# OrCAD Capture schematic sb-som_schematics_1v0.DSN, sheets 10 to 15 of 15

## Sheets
10 03. CompuLab CoM/SoM: size C; title: SB-SOM    03. CompuLab CoM/SoM
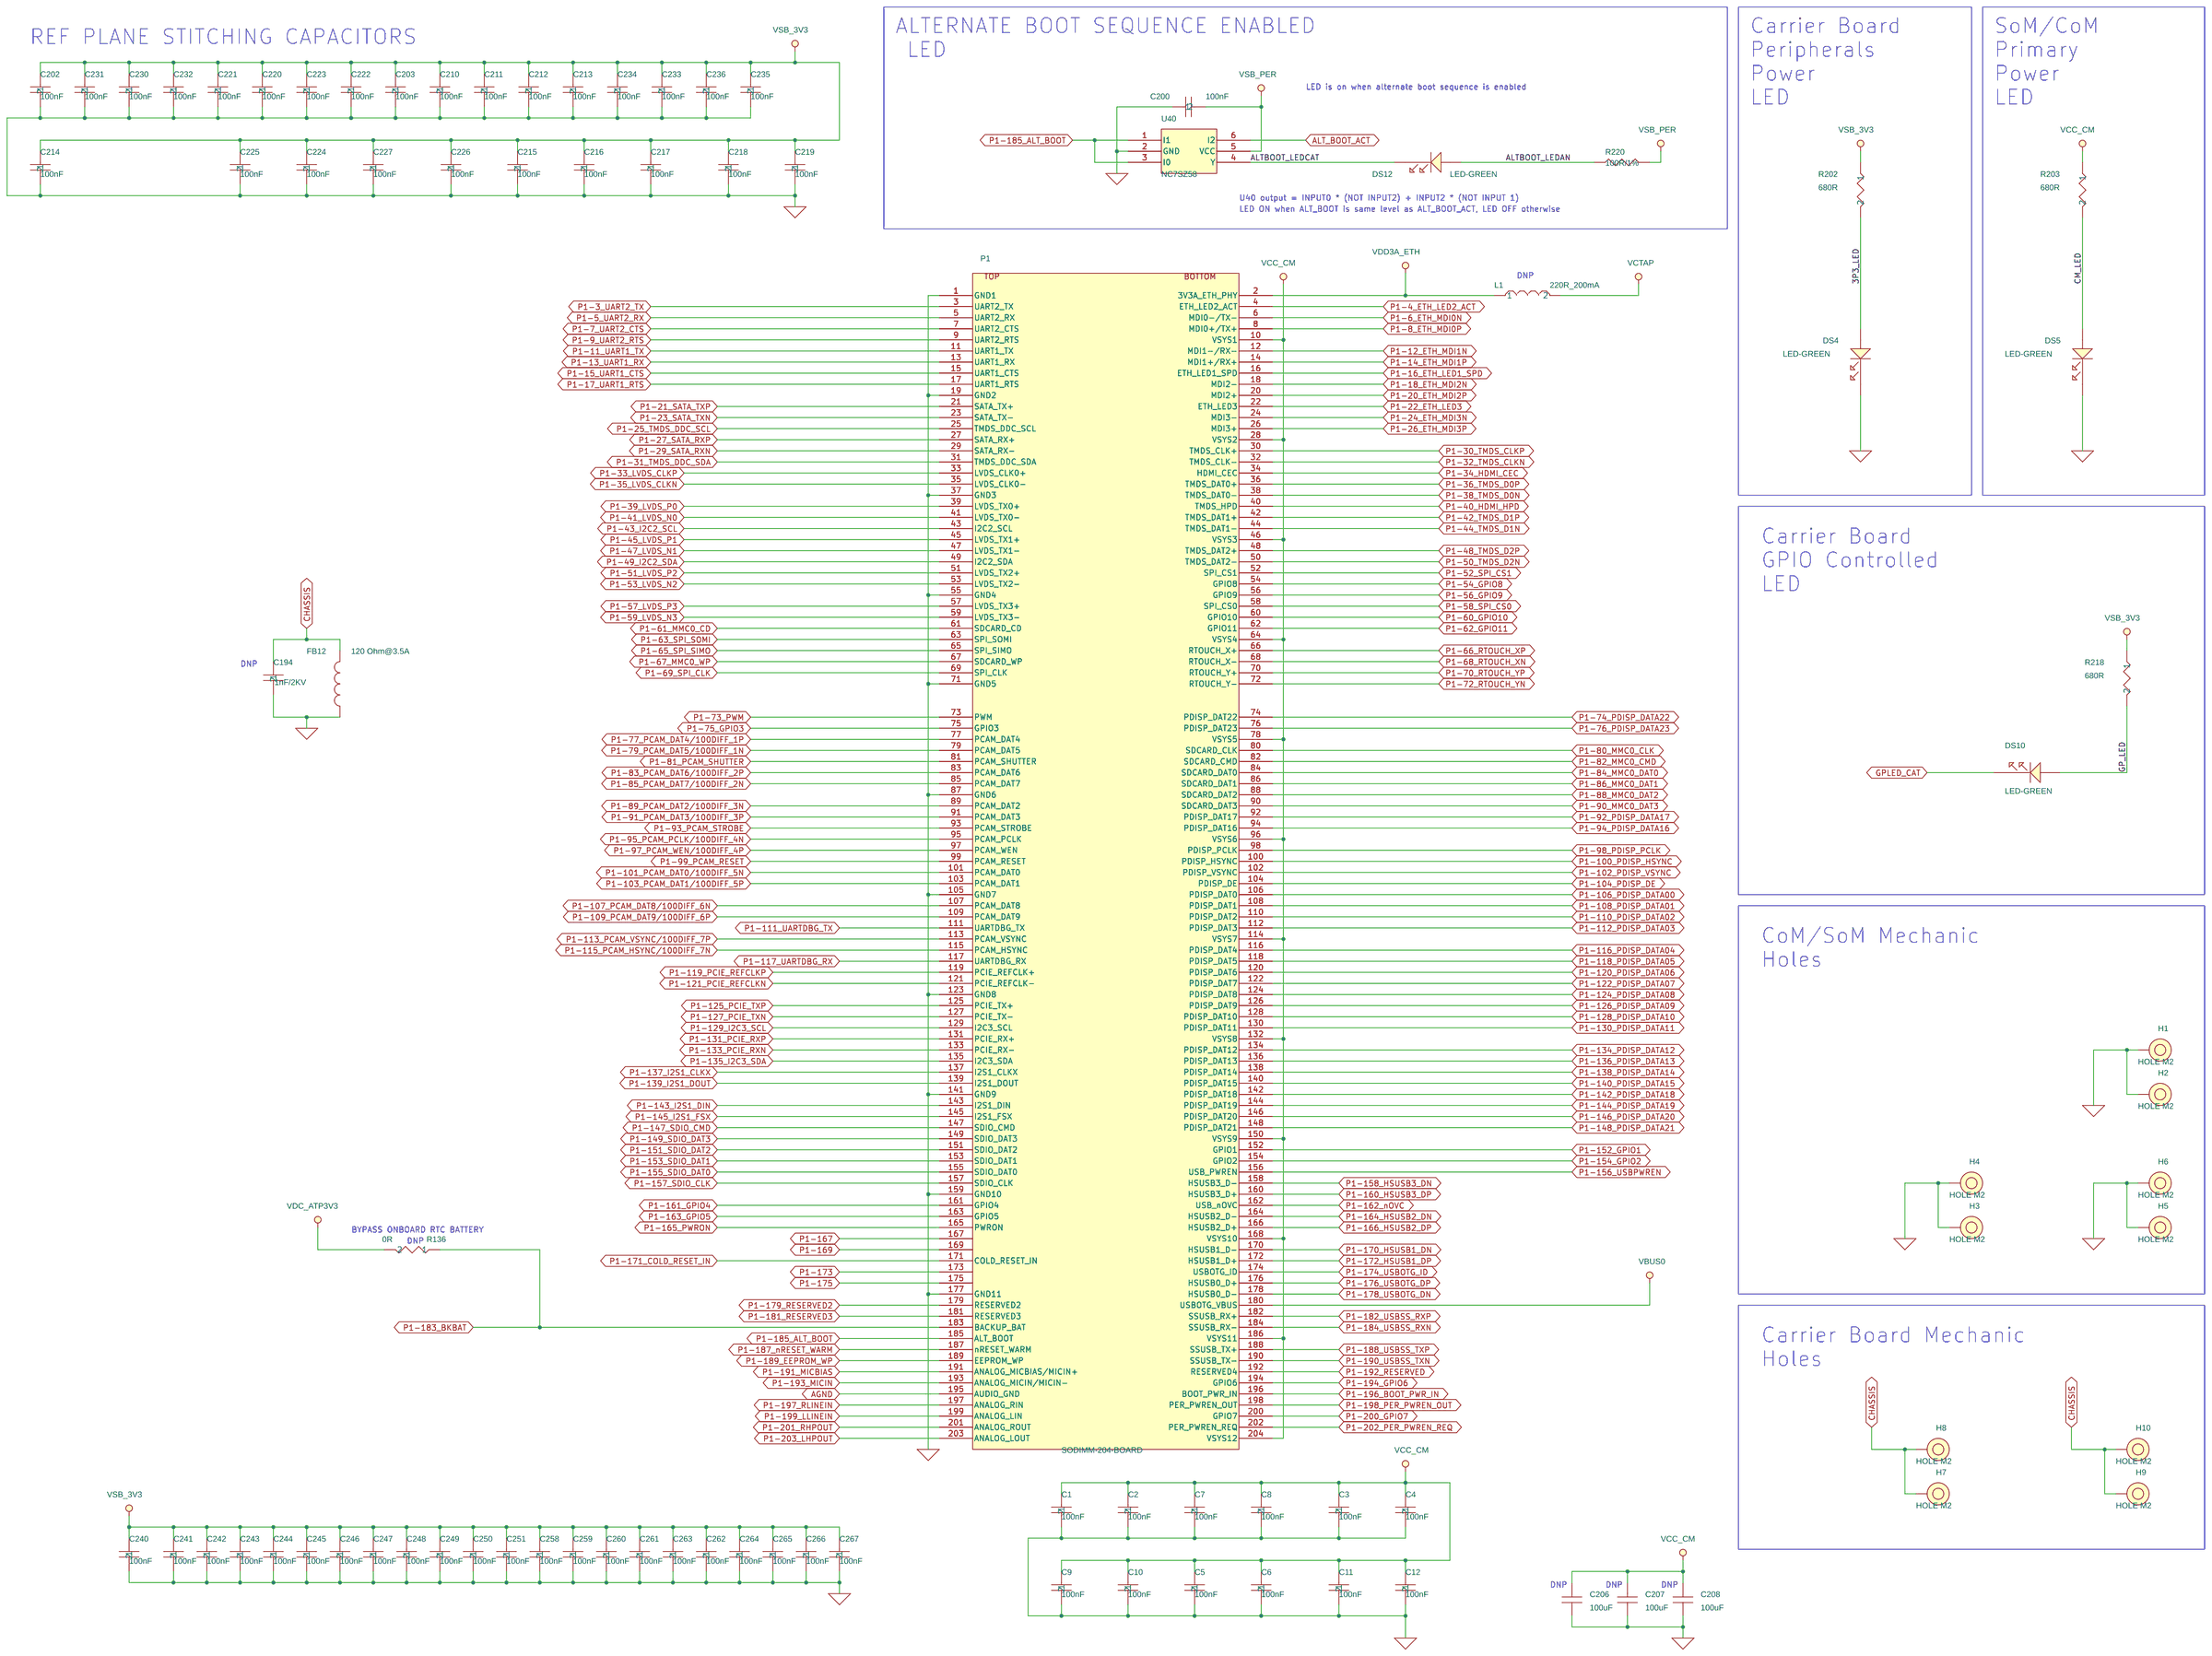
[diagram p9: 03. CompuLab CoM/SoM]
11 12. Bypass: CM-T54 Specific: size C; title: SB-SOM    12. Bypass: CM-T54 Specific
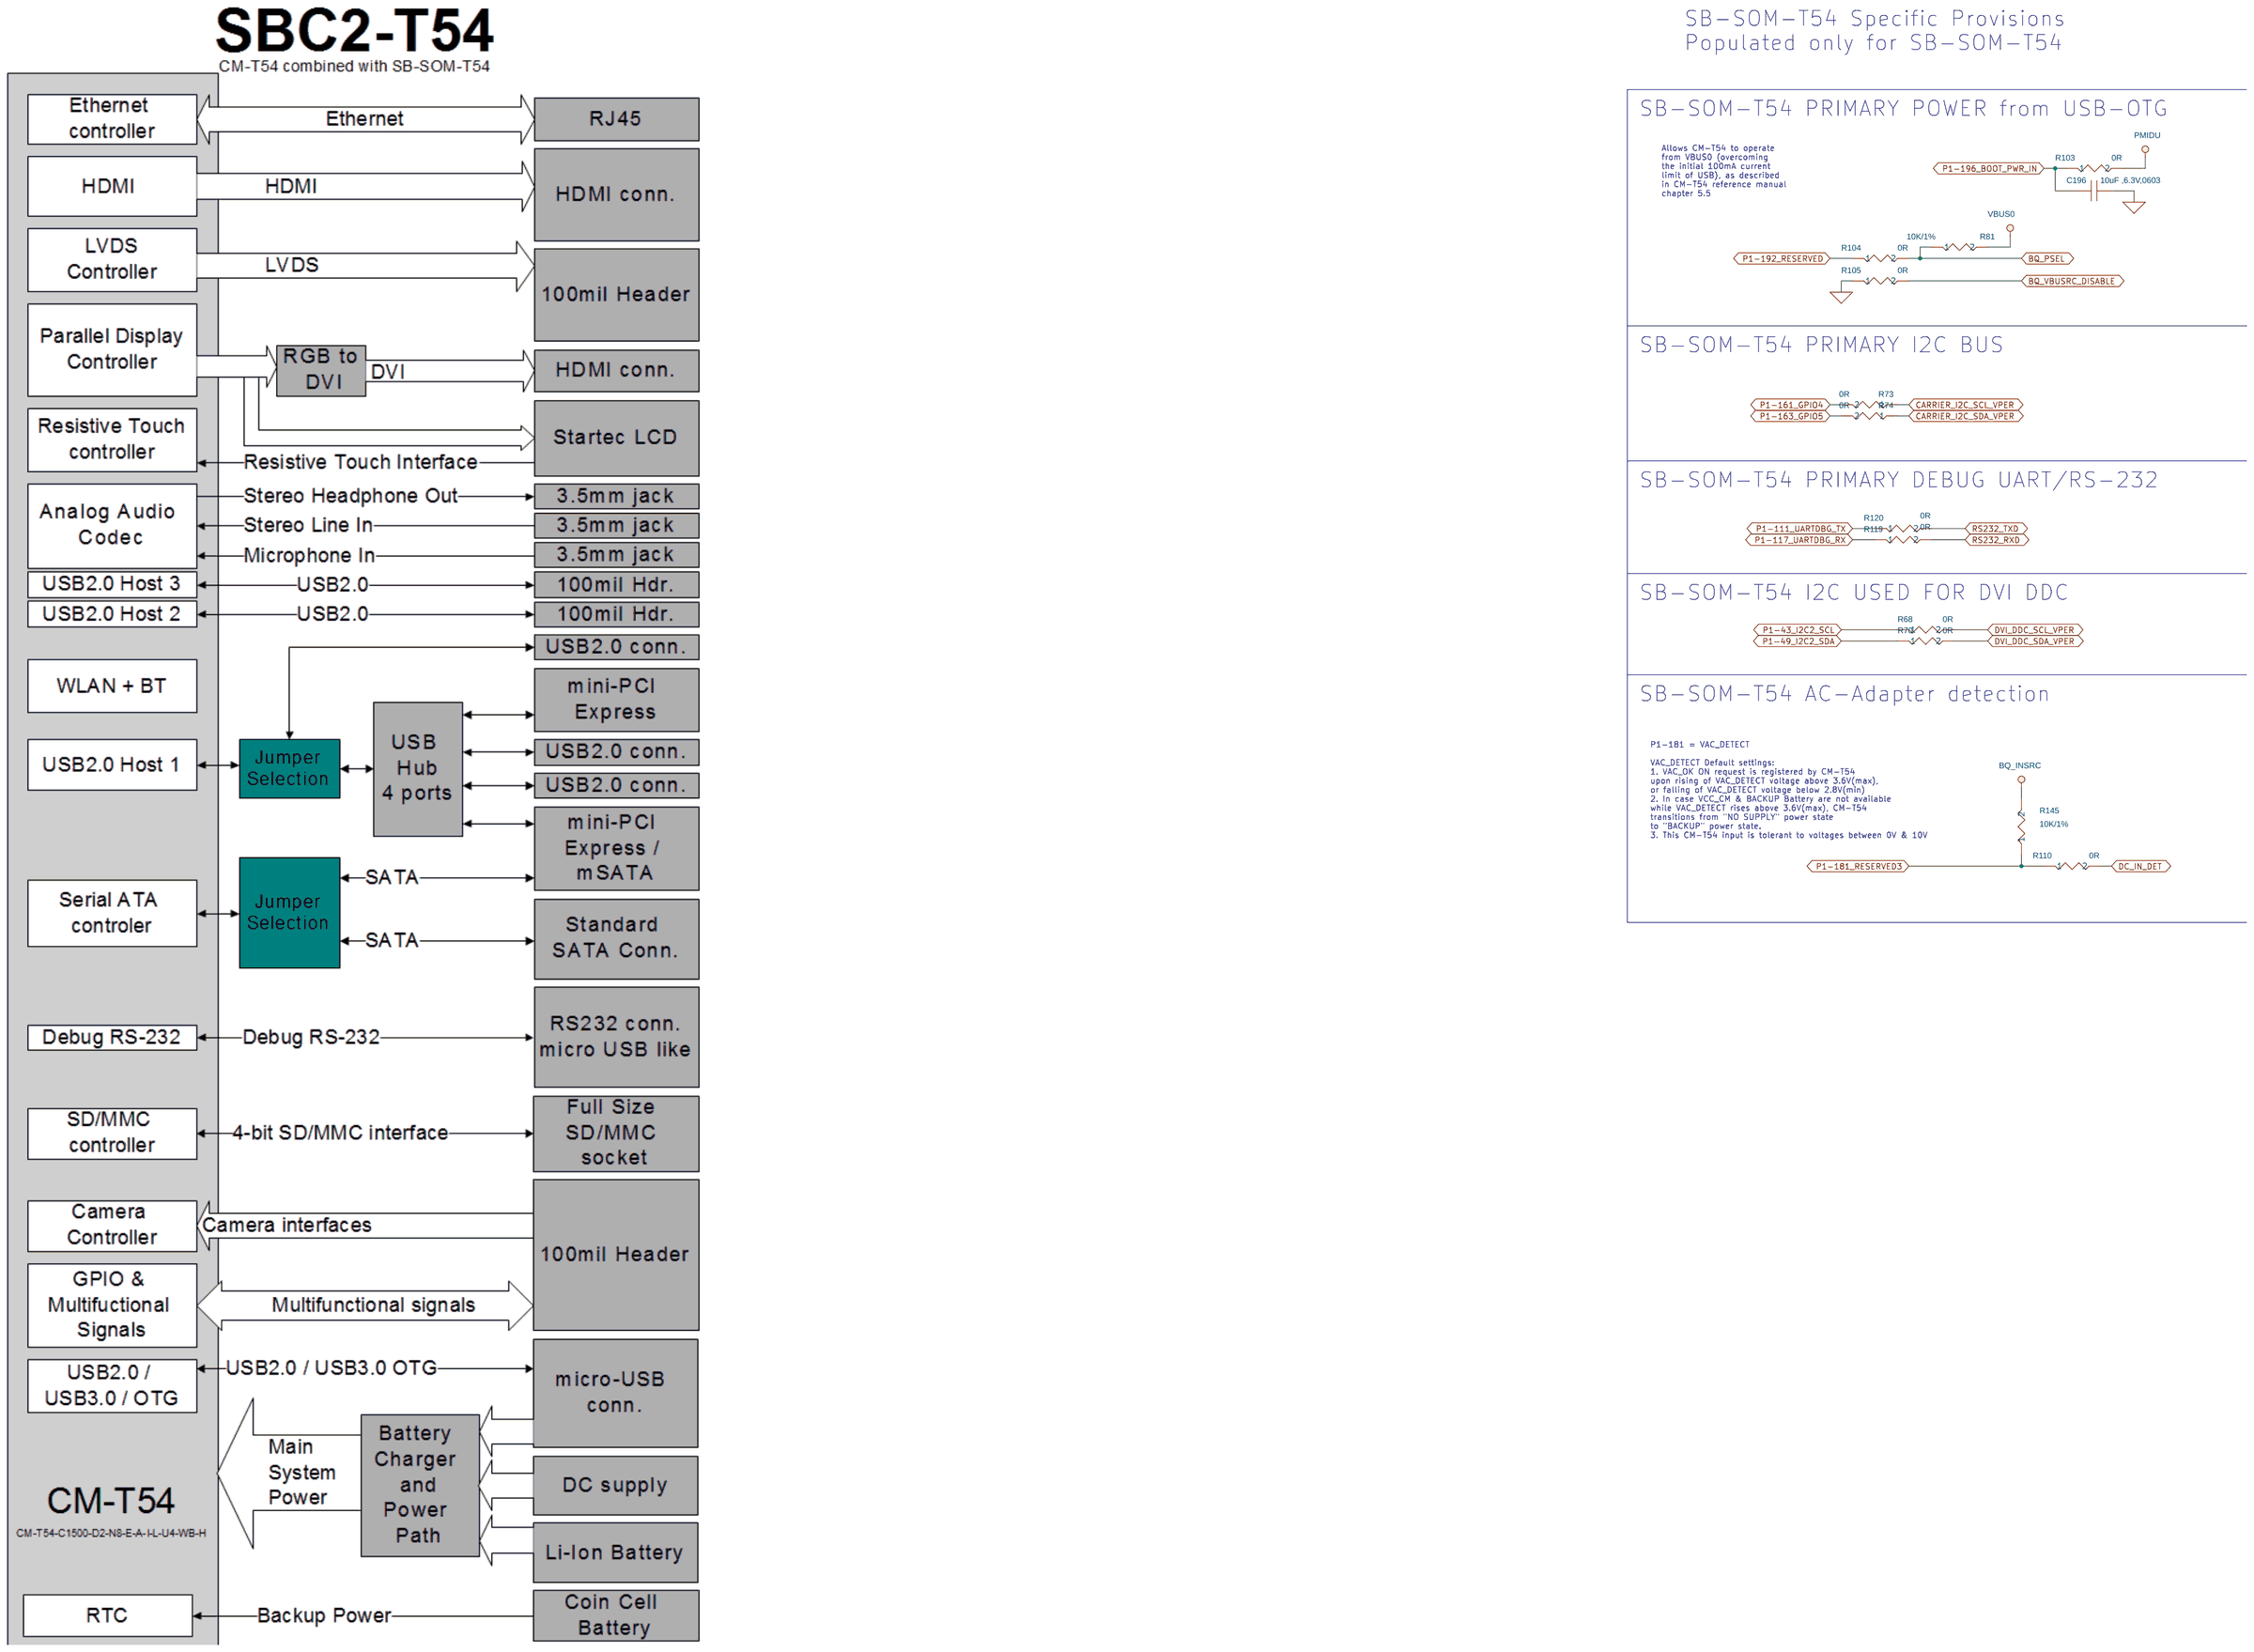
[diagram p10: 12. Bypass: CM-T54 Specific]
12 11. Bypass: non-SoM-Specific: size C; title: SB-SOM    11. Bypass: non-SoM-Specific
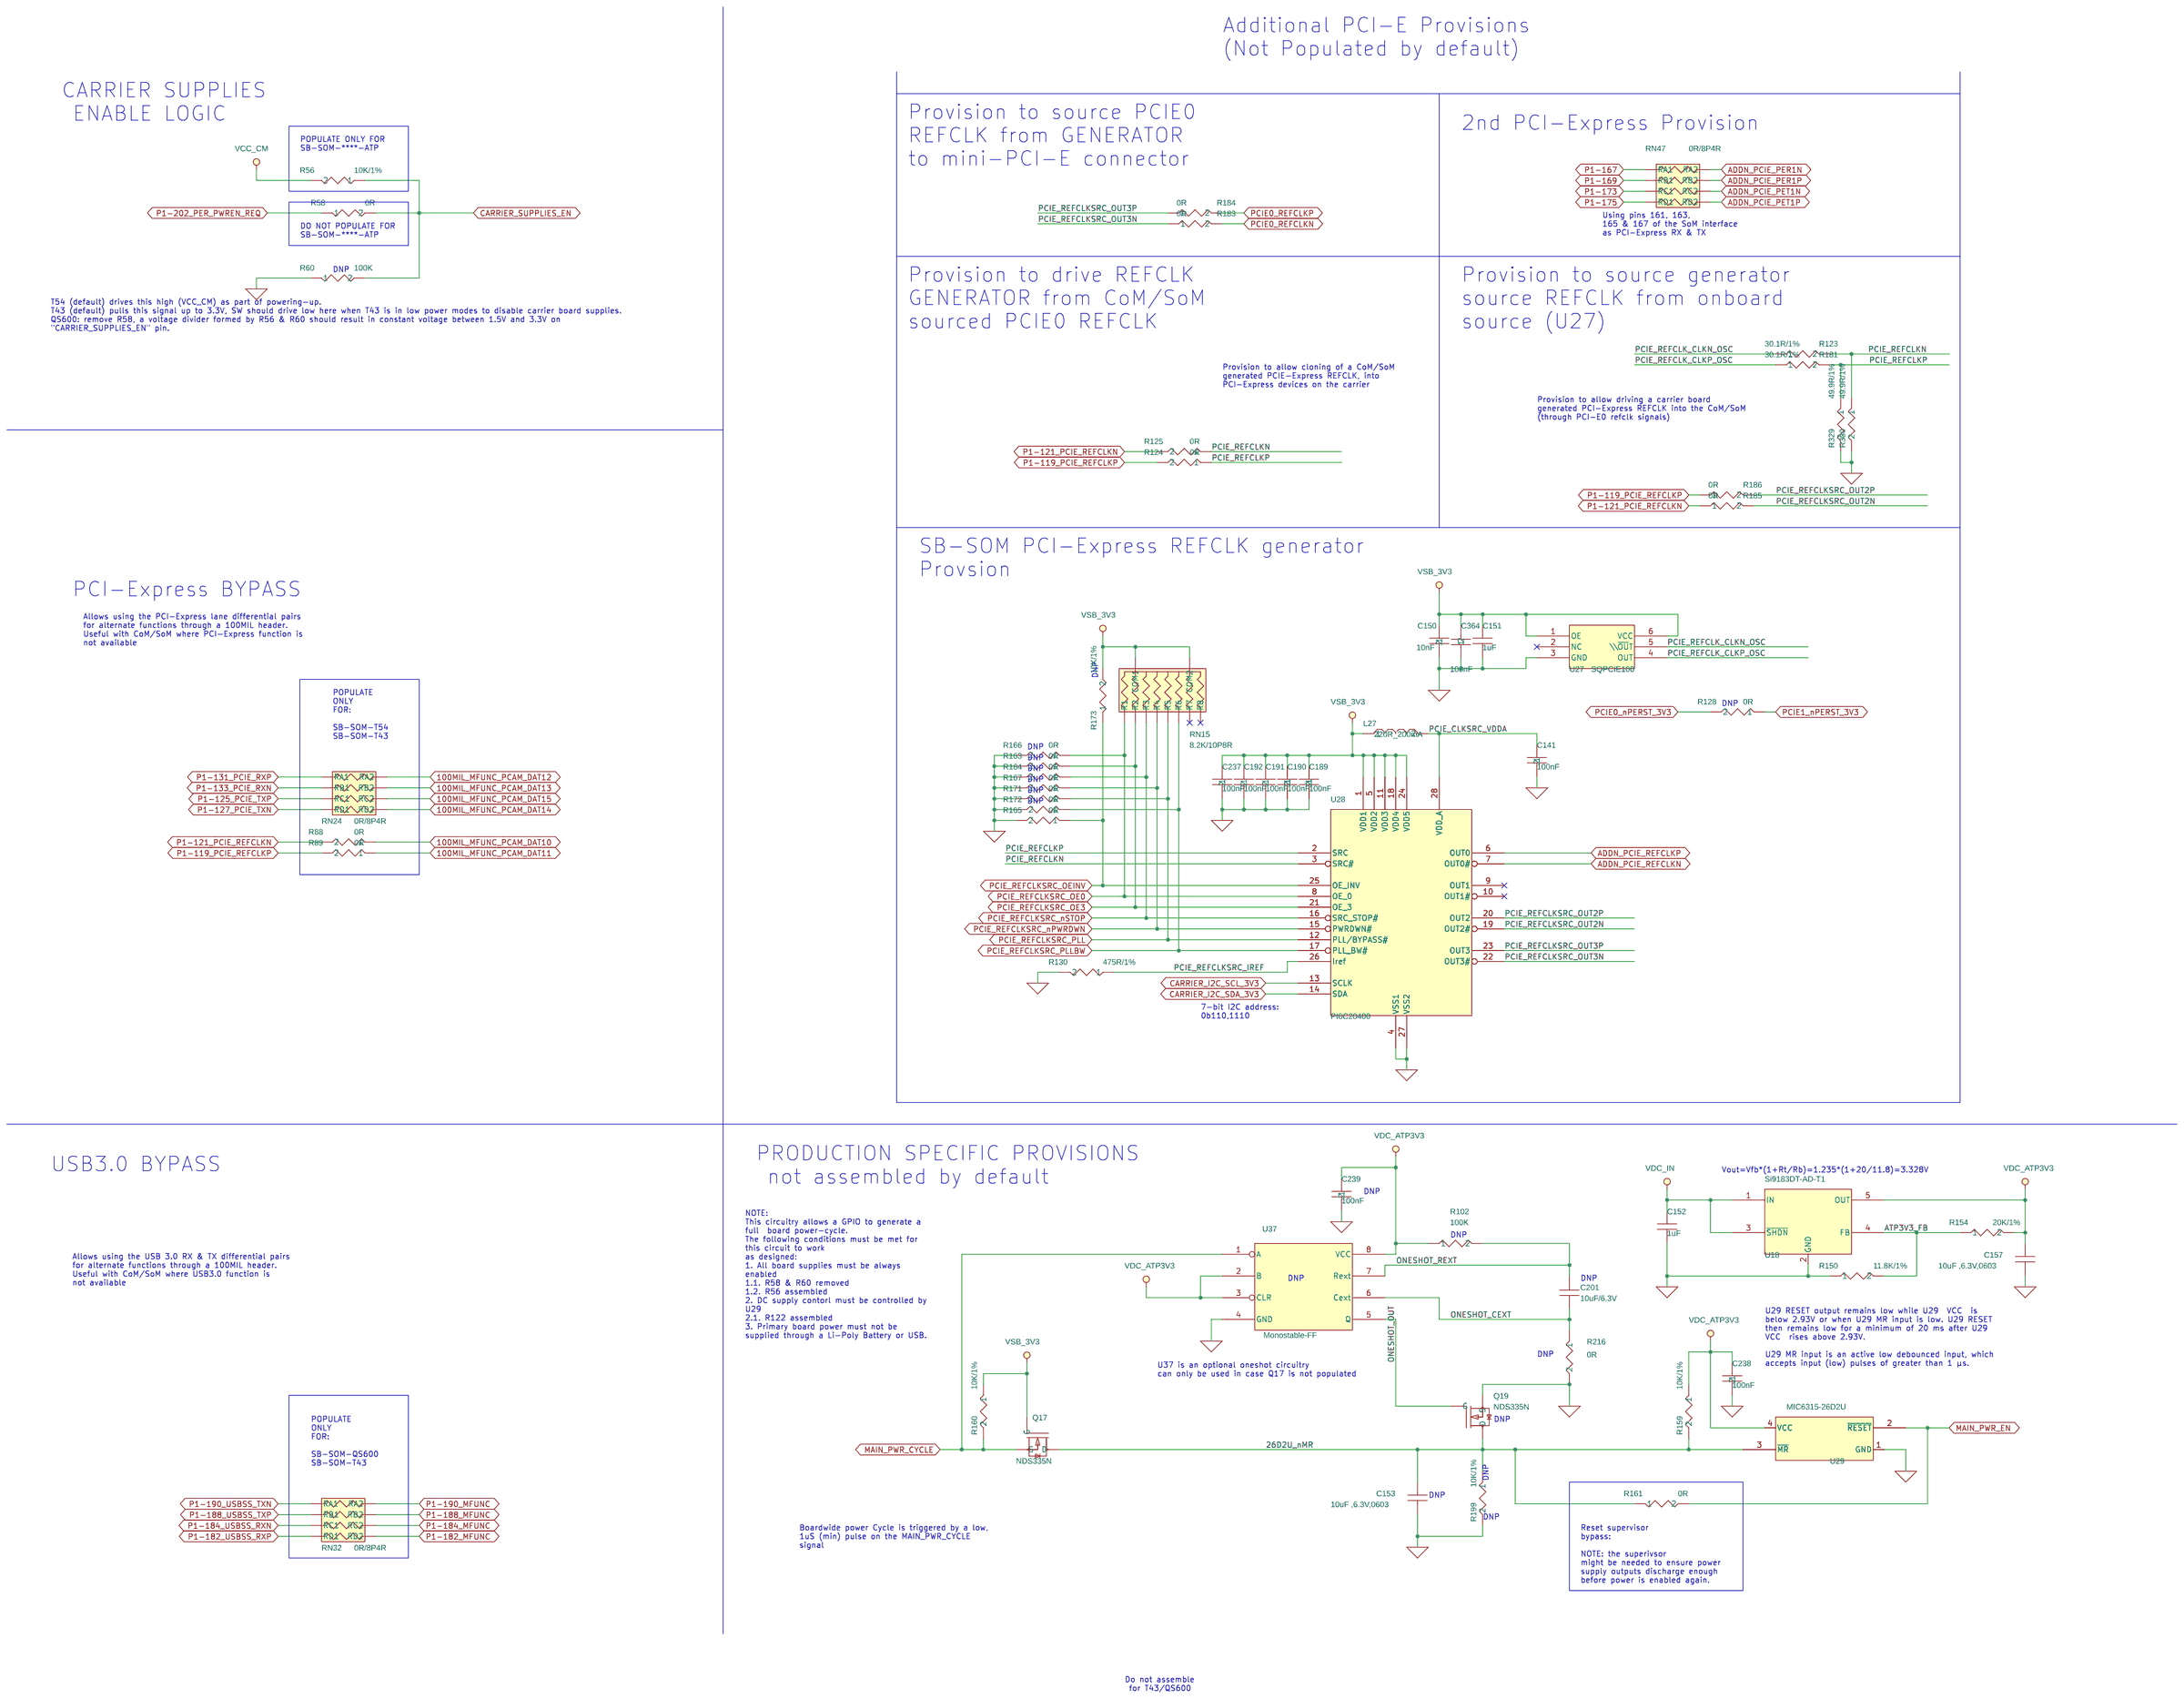
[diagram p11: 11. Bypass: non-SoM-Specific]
13 14. Bypass: CM-T43 Specific: size C; title: SB-SOM    14. Bypass: CM-T43 Specific
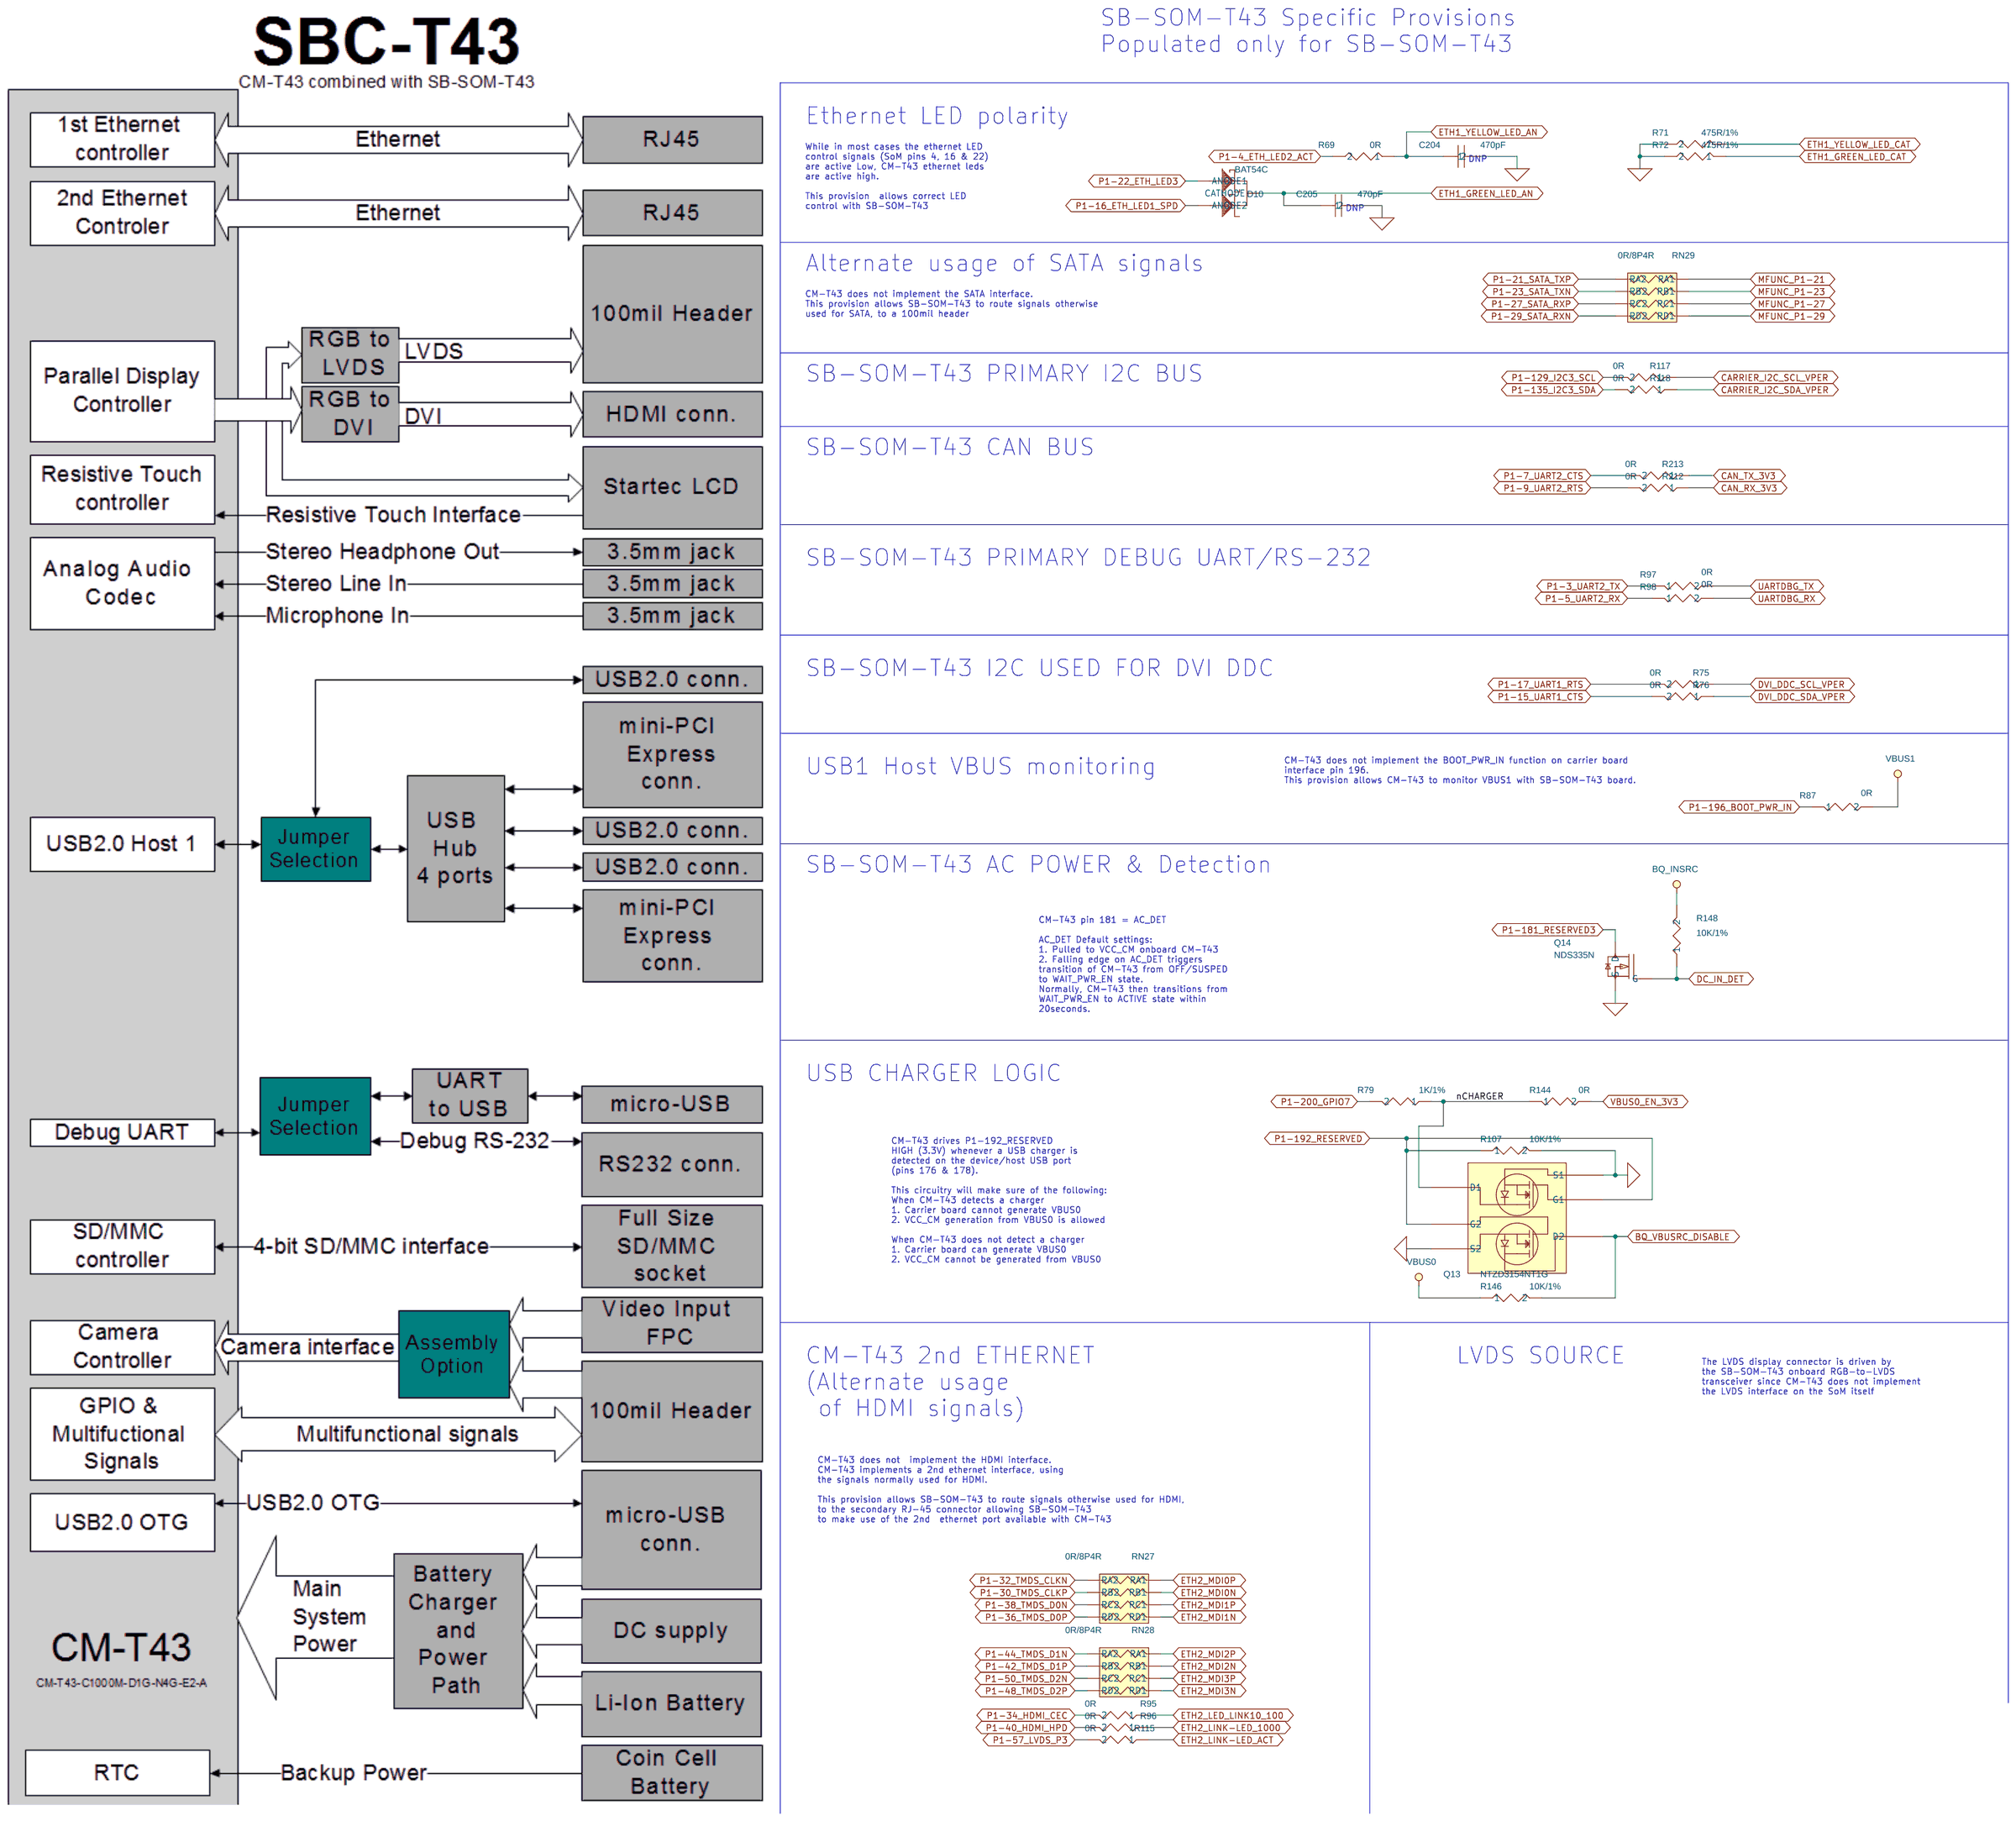
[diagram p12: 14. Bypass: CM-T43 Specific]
14 13. Bypass: CM-QS600 Specific: size C; title: SB-SOM    13. Bypass: CM-QS600 Specific
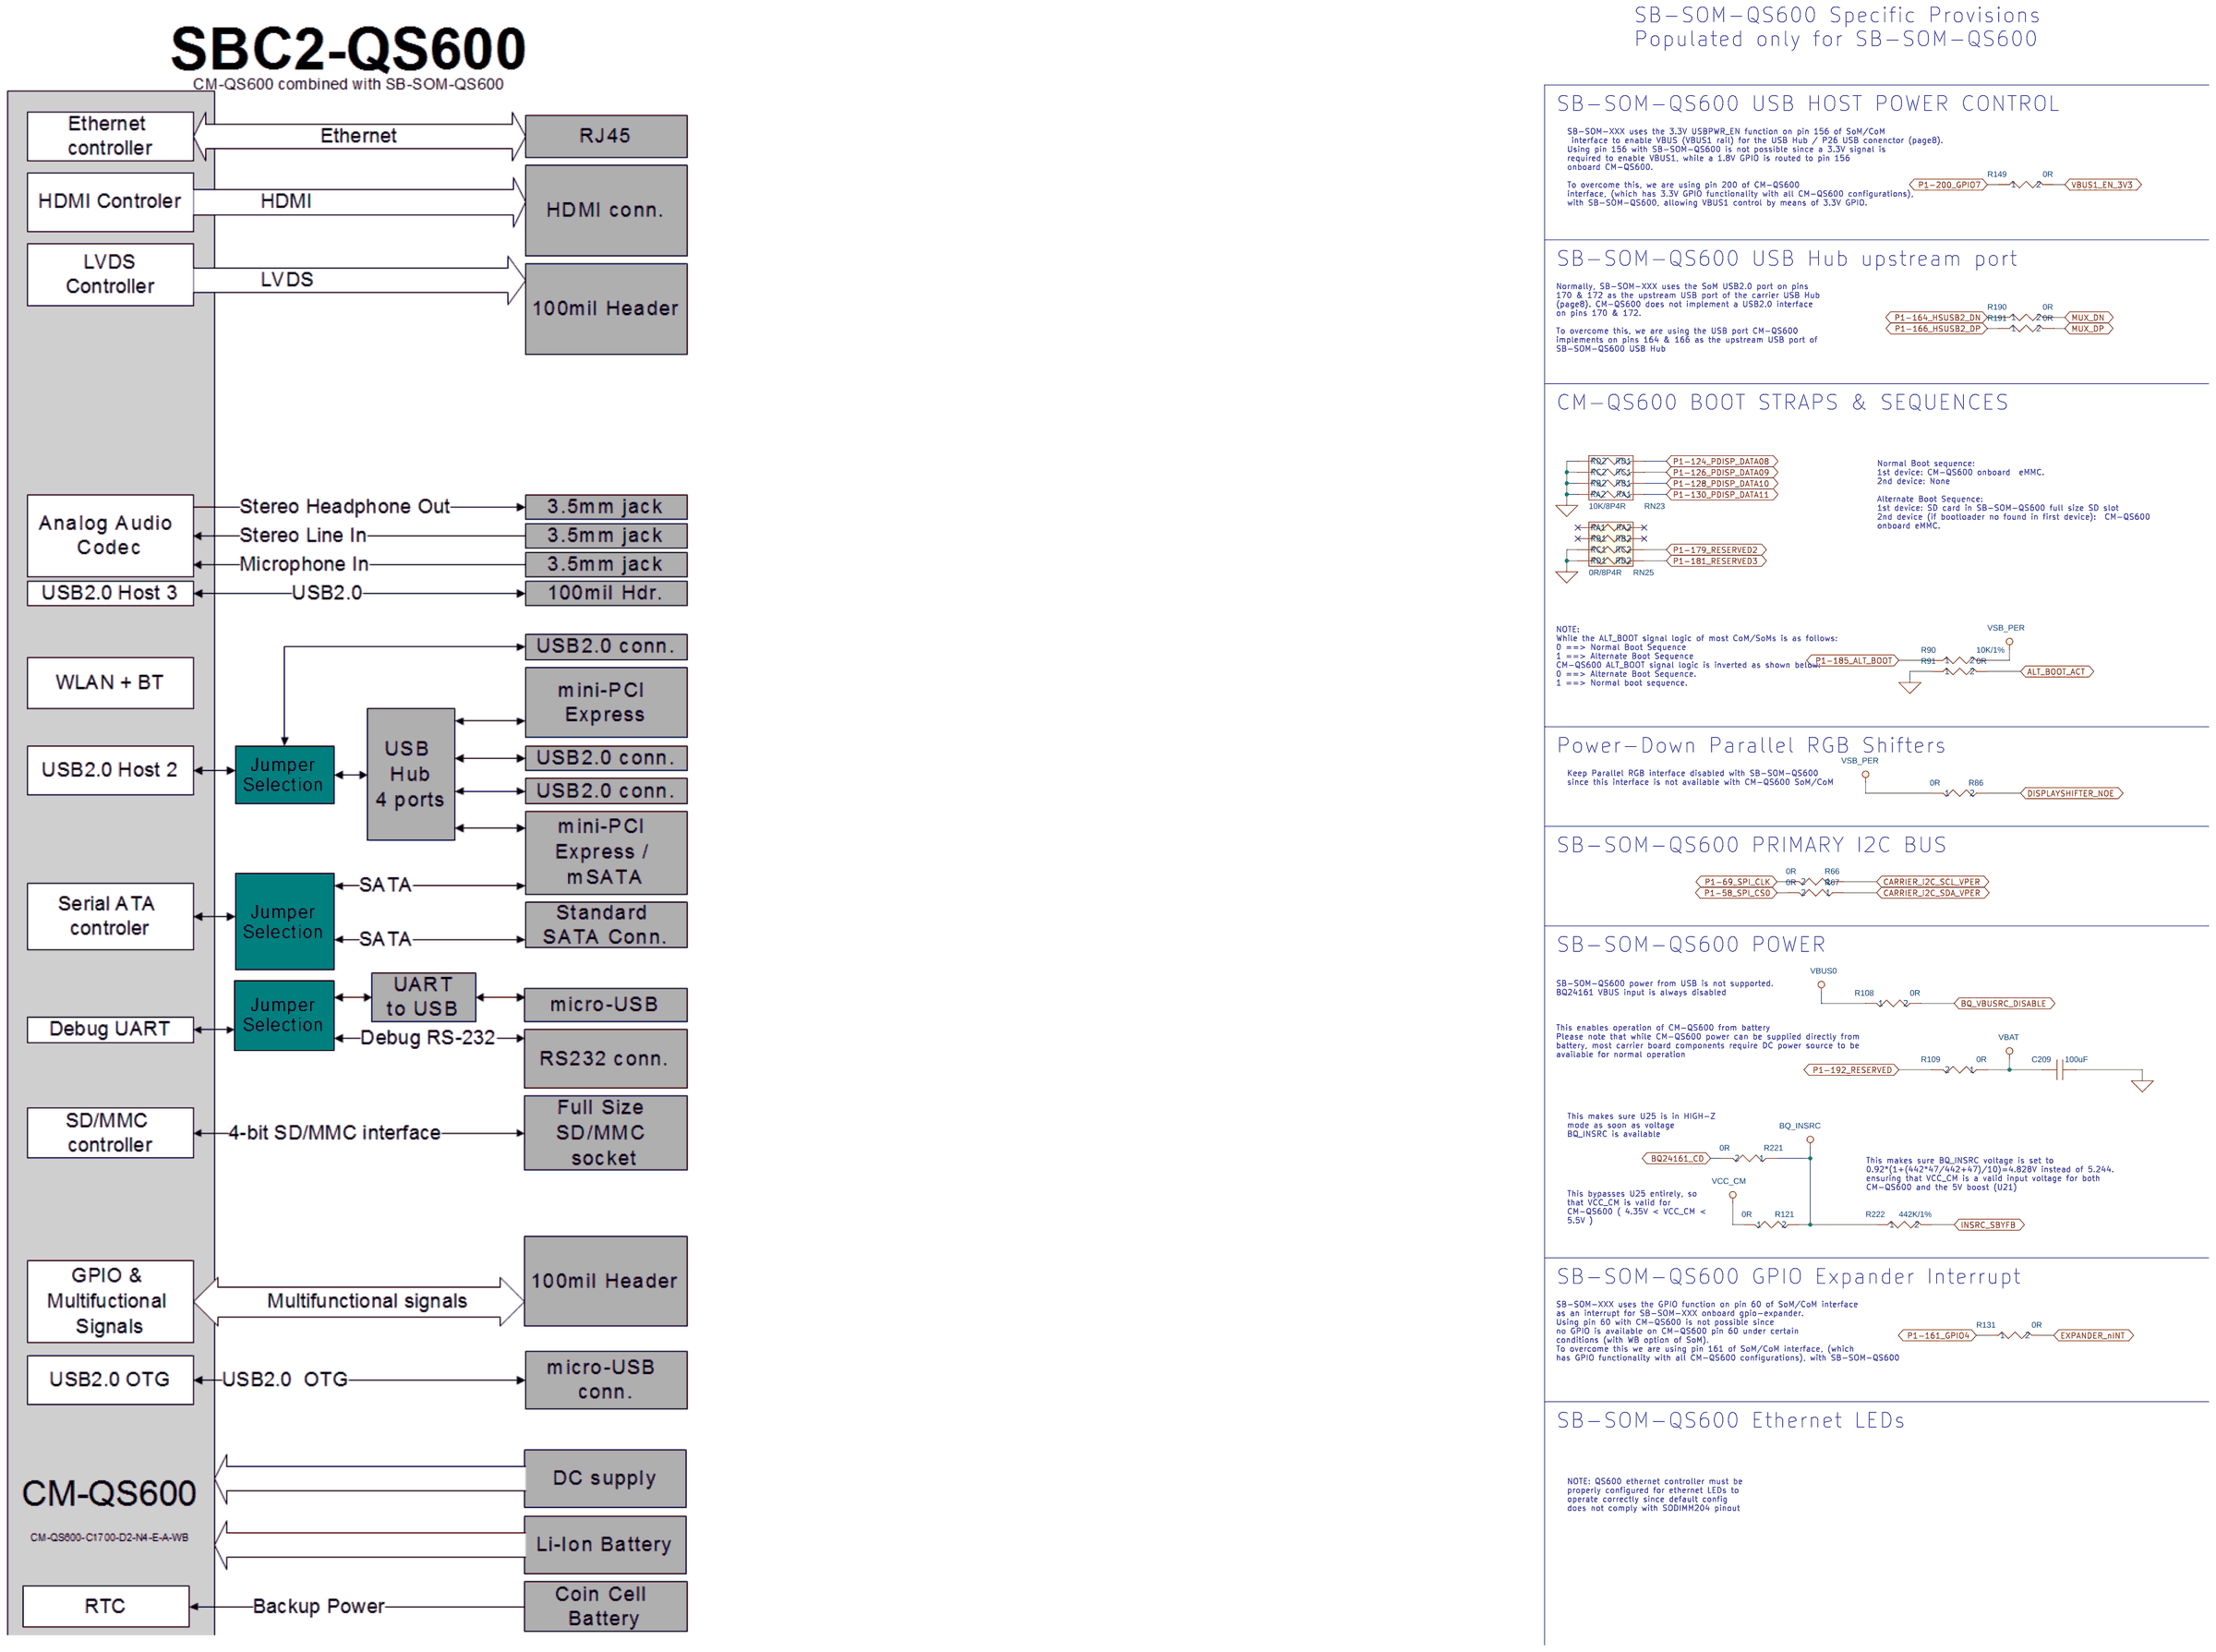
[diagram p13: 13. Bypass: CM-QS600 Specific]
15 15. Bypass: Future SoMs/CoMs: title: SB-SOM    15. Bypass: Future CoMs/SoMs
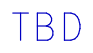
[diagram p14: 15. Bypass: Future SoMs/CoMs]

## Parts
sheet 03. CompuLab CoM/SoM
C1  100nF  [RC0402]
C2  100nF  [RC0402]
C3  100nF  [RC0402]
C4  100nF  [RC0402]
C5  100nF  [RC0402]
C6  100nF  [RC0402]
C7  100nF  [RC0402]
C8  100nF  [RC0402]
C9  100nF  [RC0402]
C10  100nF  [RC0402]
C11  100nF  [RC0402]
C12  100nF  [RC0402]
C194  1nF/2KV  [C1812]
C200  100nF  [RC0402]
C202  100nF  [RC0402]
C203  100nF  [RC0402]
C206  100uF  [C1206]
C207  100uF  [C1206]
C208  100uF  [C1206]
C210  100nF  [RC0402]
C211  100nF  [RC0402]
C212  100nF  [RC0402]
C213  100nF  [RC0402]
C214  100nF  [RC0402]
C215  100nF  [RC0402]
C216  100nF  [RC0402]
C217  100nF  [RC0402]
C218  100nF  [RC0402]
C219  100nF  [RC0402]
C220  100nF  [RC0402]
C221  100nF  [RC0402]
C222  100nF  [RC0402]
C223  100nF  [RC0402]
C224  100nF  [RC0402]
C225  100nF  [RC0402]
C226  100nF  [RC0402]
C227  100nF  [RC0402]
C230  100nF  [RC0402]
C231  100nF  [RC0402]
C232  100nF  [RC0402]
C233  100nF  [RC0402]
C234  100nF  [RC0402]
C235  100nF  [RC0402]
C236  100nF  [RC0402]
C240  100nF  [RC0402]
C241  100nF  [RC0402]
C242  100nF  [RC0402]
C243  100nF  [RC0402]
C244  100nF  [RC0402]
C245  100nF  [RC0402]
C246  100nF  [RC0402]
C247  100nF  [RC0402]
C248  100nF  [RC0402]
C249  100nF  [RC0402]
C250  100nF  [RC0402]
C251  100nF  [RC0402]
C258  100nF  [RC0402]
C259  100nF  [RC0402]
C260  100nF  [RC0402]
C261  100nF  [RC0402]
C262  100nF  [RC0402]
C263  100nF  [RC0402]
C264  100nF  [RC0402]
C265  100nF  [RC0402]
C266  100nF  [RC0402]
C267  100nF  [RC0402]
DS4  LED-GREEN  [LED-1206]
DS5  LED-GREEN  [LED-1206]
DS10  LED-GREEN  [LED-1206]
DS12  LED-GREEN  [LED-1206]
FB12  120 Ohm@3.5A  [1206]
H1  HOLE M2  [M2PAD]
H2  HOLE M2  [M2PAD]
H3  HOLE M2  [M2PAD]
H4  HOLE M2  [M2PAD]
H5  HOLE M2  [M2PAD]
H6  HOLE M2  [M2PAD]
H7  HOLE M2  [M2PAD]
H8  HOLE M2  [M2PAD]
H9  HOLE M2  [M2PAD]
H10  HOLE M2  [M2PAD]
L1  220R_200mA  [FB0402]
P1  SODIMM-204-BOARD  [190I20400S]
R136  0R  [RC0402]
R202  680R  [RC0402]
R203  680R  [RC0402]
R218  680R  [RC0402]
R220  100R/1%  [RC0402]
U40  NC7SZ58  [MO-252UAAD]
sheet 11. Bypass: non-SoM-Specific
C141  100nF  [RC0402]
C150  10nF  [RC0402]
C151  1uF  [RC0402]
C152  1uF  [RC0402]
C153  10uF ,6.3V,0603  [C0603-08]
C157  10uF ,6.3V,0603  [C0603-08]
C189  100nF  [RC0402]
C190  100nF  [RC0402]
C191  100nF  [RC0402]
C192  100nF  [RC0402]
C201  10uF/6.3V  [RC0603]
C237  100nF  [RC0402]
C238  100nF  [RC0402]
C239  100nF  [RC0402]
C364  100nF  [RC0402]
L27  220R_200mA  [FB0402]
Q17  NDS335N  [SOT23]
Q19  NDS335N  [SOT23]
R56  10K/1%  [RC0402]
R58  0R  [RC0402]
R60  100K  [RC0402]
R88  0R  [RC0402]
R89  0R  [RC0402]
R102  100K  [RC0402]
R123  30.1R/1%  [RC0402]
R124  0R  [RC0402]
R125  0R  [RC0402]
R128  0R  [RC0402]
R130  475R/1%  [RC0402]
R150  11.8K/1%  [RC0402]
R154  20K/1%  [RC0402]
R159  10K/1%  [RC0402]
R160  10K/1%  [RC0402]
R161  0R  [RC0402]
R163  0R  [RC0402]
R164  0R  [RC0402]
R165  0R  [RC0402]
R166  0R  [RC0402]
R167  0R  [RC0402]
R171  0R  [RC0402]
R172  0R  [RC0402]
R173  10K/1%  [RC0402]
R181  30.1R/1%  [RC0402]
R183  0R  [RC0402]
R184  0R  [RC0402]
R185  0R  [RC0402]
R186  0R  [RC0402]
R199  10K/1%  [RC0402]
R216  0R  [RC0402]
R329  49.9R/1%  [RC0402]
R330  49.9R/1%  [RC0402]
RN15  8.2K/10P8R  [RESNET10P1206]
RN24  0R/8P4R  [RESNET8P0805]
RN32  0R/8P4R  [RESNET8P0805]
RN47  0R/8P4R  [RESNET8P0805]
U18  Si9183DT-AD-T1  [SOT23-5]
U27  SQPCIE100  [OSC5x3.2-6]
U28  PI6C20400  [TSSOP28-6_5-_65]
U29  MIC6315-26D2U  [SOT-143]
U37  Monostable-FF  [MO-187CA-8]
sheet 12. Bypass: CM-T54 Specific
C196  10uF ,6.3V,0603  [C0603-08]
R68  0R  [RC0402]
R70  0R  [RC0402]
R73  0R  [RC0402]
R74  0R  [RC0402]
R81  10K/1%  [RC0402]
R103  0R  [RC0402]
R104  0R  [RC0402]
R105  0R  [RC0402]
R110  0R  [RC0402]
R119  0R  [RC0402]
R120  0R  [RC0402]
R145  10K/1%  [RC0402]
sheet 13. Bypass: CM-QS600 Specific
C209  100uF  [C1206]
R66  0R  [RC0402]
R67  0R  [RC0402]
R86  0R  [RC0402]
R90  10K/1%  [RC0402]
R91  0R  [RC0402]
R108  0R  [RC0402]
R109  0R  [RC1206]
R121  0R  [RC1206]
R131  0R  [RC0402]
R149  0R  [RC0402]
R190  0R  [RC0402]
R191  0R  [RC0402]
R221  0R  [RC0402]
R222  442K/1%  [RC0402]
RN23  10K/8P4R  [RESNET8P0805]
RN25  0R/8P4R  [RESNET8P0805]
sheet 14. Bypass: CM-T43 Specific
C204  470pF  [RC0603]
C205  470pF  [RC0603]
D10  BAT54C  [SOT23]
Q13  NTZD3154NT1G  [SOT-563]
Q14  NDS335N  [SOT23]
R69  0R  [RC0402]
R71  475R/1%  [RC0402]
R72  475R/1%  [RC0402]
R75  0R  [RC0402]
R76  0R  [RC0402]
R79  1K/1%  [RC0402]
R87  0R  [RC0402]
R95  0R  [RC0402]
R96  0R  [RC0402]
R97  0R  [RC0402]
R98  0R  [RC0402]
R107  10K/1%  [RC0402]
R115  0R  [RC0402]
R117  0R  [RC0402]
R118  0R  [RC0402]
R144  0R  [RC0402]
R146  10K/1%  [RC0402]
R148  10K/1%  [RC0402]
R212  0R  [RC0402]
R213  0R  [RC0402]
RN27  0R/8P4R  [RESNET8P0805]
RN28  0R/8P4R  [RESNET8P0805]
RN29  0R/8P4R  [RESNET8P0805]

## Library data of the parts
C1 = 100nF,_10V,_X7R,_10%,_0402_51: CLABCONF0: = SB-SOM
C2 = 100nF,_10V,_X7R,_10%,_0402_36: CLABCONF0: = SB-SOM
C3 = 100nF,_10V,_X7R,_10%,_0402_57: CLABCONF0: = SB-SOM
C4 = 100nF,_10V,_X7R,_10%,_0402_41: CLABCONF0: = SB-SOM
C5 = 100nF,_10V,_X7R,_10%,_0402_59: CLABCONF0: = SB-SOM
C6 = 100nF,_10V,_X7R,_10%,_0402_45: CLABCONF0: = SB-SOM
C7 = 100nF,_10V,_X7R,_10%,_0402_26: CLABCONF0: = SB-SOM
C8 = 100nF,_10V,_X7R,_10%,_0402_9: CLABCONF0: = SB-SOM
C9 = 100nF,_10V,_X7R,_10%,_0402_27: CLABCONF0: = SB-SOM
C10 = 100nF,_10V,_X7R,_10%,_0402_11: CLABCONF0: = SB-SOM
C11 = 100nF,_10V,_X7R,_10%,_0402_30: CLABCONF0: = SB-SOM
C12 = 100nF,_10V,_X7R,_10%,_0402_17: CLABCONF0: = SB-SOM
C194 = 1nF,_2KV,SMD_1812,_X7R,_10%: CLABCONF0: DNP
C200 = 100nF,_10V,_X7R,_10%,_0402_50: CLABCONF0: = SB-SOM
C202 = 100nF,_10V,_X7R,_10%,_0402_15: CLABCONF0: = SB-SOM
C203 = 100nF,_10V,_X7R,_10%,_0402_42: CLABCONF0: = SB-SOM
C206-C208 = 100uF,_6.3V,_X5R,_20%,_1210: CLABCONF0: DNP; P/N: 151B10730S
C210 = 100nF,_10V,_X7R,_10%,_0402_10: CLABCONF0: = SB-SOM
C211 = 100nF,_10V,_X7R,_10%,_0402_39: CLABCONF0: = SB-SOM
C212 = 100nF,_10V,_X7R,_10%,_0402_8: CLABCONF0: = SB-SOM
C213 = 100nF,_10V,_X7R,_10%,_0402_38: CLABCONF0: = SB-SOM
C214 = 100nF,_10V,_X7R,_10%,_0402_7: CLABCONF0: = SB-SOM
C215 = 100nF,_10V,_X7R,_10%,_0402_35: CLABCONF0: = SB-SOM
C216 = 100nF,_10V,_X7R,_10%,_0402_3: CLABCONF0: = SB-SOM
C217 = 100nF,_10V,_X7R,_10%,_0402_52: CLABCONF0: = SB-SOM
C218 = 100nF,_10V,_X7R,_10%,_0402_19: CLABCONF0: = SB-SOM
C219 = 100nF,_10V,_X7R,_10%,_0402_55: CLABCONF0: = SB-SOM
C220 = 100nF,_10V,_X7R,_10%,_0402_24: CLABCONF0: = SB-SOM
C221 = 100nF,_10V,_X7R,_10%,_0402_53: CLABCONF0: = SB-SOM
C222 = 100nF,_10V,_X7R,_10%,_0402_21: CLABCONF0: = SB-SOM
C223 = 100nF,_10V,_X7R,_10%,_0402_47: CLABCONF0: = SB-SOM
C224 = 100nF,_10V,_X7R,_10%,_0402_32: CLABCONF0: = SB-SOM
C225 = 100nF,_10V,_X7R,_10%,_0402: CLABCONF0: = SB-SOM
C226 = 100nF,_10V,_X7R,_10%,_0402_28: CLABCONF0: = SB-SOM
C227 = 100nF,_10V,_X7R,_10%,_0402_61: CLABCONF0: = SB-SOM
C230 = 100nF,_10V,_X7R,_10%,_0402_33: CLABCONF0: = SB-SOM
C231 = 100nF,_10V,_X7R,_10%,_0402_1: CLABCONF0: = SB-SOM
C232 = 100nF,_10V,_X7R,_10%,_0402_5: CLABCONF0: = SB-SOM
C233 = 100nF,_10V,_X7R,_10%,_0402_37: CLABCONF0: = SB-SOM
C234 = 100nF,_10V,_X7R,_10%,_0402_6: CLABCONF0: = SB-SOM
C235 = 100nF,_10V,_X7R,_10%,_0402_34: CLABCONF0: = SB-SOM
C236 = 100nF,_10V,_X7R,_10%,_0402_2: CLABCONF0: = SB-SOM
C240 = 100nF,_10V,_X7R,_10%,_0402_58: CLABCONF0: = SB-SOM
C241 = 100nF,_10V,_X7R,_10%,_0402_25: CLABCONF0: = SB-SOM
C242 = 100nF,_10V,_X7R,_10%,_0402_54: CLABCONF0: = SB-SOM
C243 = 100nF,_10V,_X7R,_10%,_0402_22: CLABCONF0: = SB-SOM
C244 = 100nF,_10V,_X7R,_10%,_0402_48: CLABCONF0: = SB-SOM
C245 = 100nF,_10V,_X7R,_10%,_0402_16: CLABCONF0: = SB-SOM
C246 = 100nF,_10V,_X7R,_10%,_0402_43: CLABCONF0: = SB-SOM
C247 = 100nF,_10V,_X7R,_10%,_0402_12: CLABCONF0: = SB-SOM
C248 = 100nF,_10V,_X7R,_10%,_0402_40: CLABCONF0: = SB-SOM
C249 = 100nF,_10V,_X7R,_10%,_0402_29: CLABCONF0: = SB-SOM
C250 = 100nF,_10V,_X7R,_10%,_0402_60: CLABCONF0: = SB-SOM
C251 = 100nF,_10V,_X7R,_10%,_0402_31: CLABCONF0: = SB-SOM
C258 = 100nF,_10V,_X7R,_10%,_0402_20: CLABCONF0: = SB-SOM
C259 = 100nF,_10V,_X7R,_10%,_0402_56: CLABCONF0: = SB-SOM
C260 = 100nF,_10V,_X7R,_10%,_0402_23: CLABCONF0: = SB-SOM
C261 = 100nF,_10V,_X7R,_10%,_0402_4: CLABCONF0: = SB-SOM
C262 = 100nF,_10V,_X7R,_10%,_0402_46: CLABCONF0: = SB-SOM
C263 = 100nF,_10V,_X7R,_10%,_0402_14: CLABCONF0: = SB-SOM
C264 = 100nF,_10V,_X7R,_10%,_0402_49: CLABCONF0: = SB-SOM
C265 = 100nF,_10V,_X7R,_10%,_0402_18: CLABCONF0: = SB-SOM
C266 = 100nF,_10V,_X7R,_10%,_0402_44: CLABCONF0: = SB-SOM
C267 = 100nF,_10V,_X7R,_10%,_0402_13: CLABCONF0: = SB-SOM
DS4 DS5 DS10 DS12 = LED-GREEN_1206_3: CLABCONF0: = SB-SOM
FB12 = Ferrite_bead_,_120_Ohm@3A: CLABCONF0: = SB-SOM
H1-H10 = Hole,_Plated,_M2,_5mm._ext.: CLABCONF0: DNP
L1 = Ferrit_330R@100Mhz,0.2A: CLABCONF0: DNP; P/N: 147D22100S
P1 = SODIMM-204_30: CLABCONF0: = SB-SOM
R136 = 0R,_0402: CLABCONF0: DNP
R202 = 47K,_0402_1: CLABCONF0: = SB-SOM; P/N: 161C68001S
R203 = 47K,_0402: CLABCONF0: = SB-SOM; P/N: 161C68001S
R218 = 47K,_0402_2: CLABCONF0: = SB-SOM; P/N: 161C68001S
R220 = 100R,1%,0402,1_16W_0: CLABCONF0: = SB-SOM
U40 = MicroGate_NC7SZ57,Univ_Gate: CLABCONF0: = SB-SOM; P/N: 106C20580S
C141 = 100nF,_10V,_X7R,_10%,_0402_6: CLABCONF0: DNP; Group: LAN2
C150 = 10nF,_25V,_X7R,_10%,_0402: CLABCONF0: DNP
C151 = 1uF,X5R,6.3V,0402: CLABCONF0: DNP
C152 = 1uF,X5R,6.3V,0402: CLABCONF0: = ATP
C153 = 10uF,6.3V,0603,20%X5R_1: CLABCONF0: = ATP
C157 = 10uF,6.3V,0603,20%X5R: CLABCONF0: = ATP
C189 = 100nF,_10V,_X7R,_10%,_0402: CLABCONF0: DNP; Group: LAN2
C190 = 100nF,_10V,_X7R,_10%,_0402_5: CLABCONF0: DNP; Group: LAN2
C191 = 100nF,_10V,_X7R,_10%,_0402_2: CLABCONF0: DNP; Group: LAN2
C192 = 100nF,_10V,_X7R,_10%,_0402_8: CLABCONF0: DNP; Group: LAN2
C201 = Cap.,10uF,6.3V,0603,X5R: CLABCONF0: DNP
C237 = 100nF,_10V,_X7R,_10%,_0402_3: CLABCONF0: DNP; Group: LAN2
C238 = 100nF,_10V,_X7R,_10%,_0402_1: CLABCONF0: = ATP; Group: LAN2
C239 = 100nF,_10V,_X7R,_10%,_0402_7: CLABCONF0: DNP; Group: LAN2
C364 = 100nF,_10V,_X7R,_10%,_0402_4: CLABCONF0: DNP
L27 = Ferrit_330R@100Mhz,0.2A: CLABCONF0: = SB-SOM; P/N: 147D22100S
Q17 = N-MOSFET,NDS335N,100mOhm@2.5V: CLABCONF0: = ATP
Q19 = N-MOSFET,NDS335N,100mOhm@2.5V: CLABCONF0: DNP
R56 = 10K,1%,0402,1_16W_2: CLABCONF0: = ATP
R58 = 0R,_0402: CLABCONF0: = SB-SOM AND NOT ATP
R60 = 100K,_0402: CLABCONF0: DNP; P/N: 161C10031S
R88 = 0R,_0402_12: CLABCONF0: = T54; CLABCONF1: = T43
R89 = 0R,_0402_4: CLABCONF0: = T54; CLABCONF1: = T43
R102 = 100K,_0402_1: CLABCONF0: DNP; P/N: 161C10031S
R123 = 30.1R,1%,0402: CLABCONF0: DNP
R124 = 0R,_0402_10: CLABCONF0: DNP
R125 = 0R,_0402_1: CLABCONF0: DNP
R128 = 0R,_0402_5: CLABCONF0: DNP
R130 = 475R_1%,_0402: CLABCONF0: DNP
R150 = 100K,_0402_2: CLABCONF0: = ATP; P/N: 161C11821S
R154 = 20K_1%,_0402: CLABCONF0: = ATP; Group: AUD
R159 = 10K,1%,0402,1_16W_4: CLABCONF0: = ATP
R160 = 10K,1%,0402,1_16W: CLABCONF0: = ATP
R161 = 0R,_0402_7: CLABCONF0: DNP
R163 = 0R,_0402_9: CLABCONF0: DNP
R164 = 0R,_0402_18: CLABCONF0: DNP
R165 = 0R,_0402_6: CLABCONF0: DNP
R166 = 0R,_0402_16: CLABCONF0: DNP
R167 = 0R,_0402_11: CLABCONF0: DNP
R171 = 0R,_0402_14: CLABCONF0: DNP
R172 = 0R,_0402_8: CLABCONF0: DNP
R173 = 10K,1%,0402,1_16W_3: CLABCONF0: DNP
R181 = 30.1R,1%,0402_1: CLABCONF0: DNP
R183 = 0R,_0402_17: CLABCONF0: DNP
R184 = 0R,_0402_3: CLABCONF0: DNP
R185 = 0R,_0402_15: CLABCONF0: DNP
R186 = 0R,_0402_13: CLABCONF0: DNP
R199 = 10K,1%,0402,1_16W_1: CLABCONF0: DNP
R216 = 0R,_0402_2: CLABCONF0: DNP
R329 = 49.9R_1%,_0402_1: CLABCONF0: DNP
R330 = 49.9R_1%,_0402: CLABCONF0: DNP
RN15 = RN,8.2K,10P8R@1206: CLABCONF0: DNP
RN24 = RN,0R,8P4R@0805: CLABCONF0: = T54; CLABCONF1: = T43
RN32 = RN,0R,8P4R@0805: CLABCONF0: = T43; CLABCONF1: = QS600
RN47 = RN,0R,8P4R@0805: CLABCONF0: DNP
U18 = Si9183_ADJ_LIN_150mA_SOT-23-5: CLABCONF0: = ATP
U27 = SQPCIE100: CLABCONF0: DNP; P/N: 141C10600I
U28 = PI6C20400_0: CLABCONF0: DNP
U29 = ADM6315_RESET_1: CLABCONF0: = ATP; P/N: 117A63151S
U37 = Monostable-FF: CLABCONF0: DNP; P/N: 106H20000S
C196 = 10uF,6_0.3V,0603,20%X5R: CLABCONF0: = T54
R68 = 0R,_0402_8: CLABCONF0: = T54
R70 = 0R,_0402_5: CLABCONF0: = T54
R73 = 0R,_0402_9: CLABCONF0: = T54
R74 = 0R,_0402_4: CLABCONF0: = T54
R81 = 10K,1%,0402,1_16W_1: CLABCONF0: = T54
R103 = 0R,_0402_1: CLABCONF0: = T54
R104 = 0R,_0402_7: CLABCONF0: = T54
R105 = 0R,_0402_3: CLABCONF0: = T54
R110 = 0R,_0402: CLABCONF0: = T54
R119 = 0R,_0402_6: CLABCONF0: = T54
R120 = 0R,_0402_2: CLABCONF0: = T54
R145 = 10K,1%,0402,1_16W: CLABCONF0: = T54
C209 = 100uF,_6.3V,_X5R,_20%,_1210: CLABCONF0: = QS600; P/N: 151B10730S
R66 = 0R,_0402_5: CLABCONF0: = QS600
R67 = 0R,_0402_1: CLABCONF0: = QS600
R86 = 0R,_0402_6: CLABCONF0: = QS600
R90 = 10K,1%,0402,1_16W: CLABCONF0: = QS600
R91 = 0R,_0402_4: CLABCONF0: = QS600
R108 = 0R,_0402_9: CLABCONF0: = QS600
R109 = 0R,_1206_1: CLABCONF0: = QS600; CLABCONF2: <null>; CLABCONF3: <null>; CLABCONF4: <null>
R121 = 0R,_1206: CLABCONF0: = QS600
R131 = 0R,_0402: CLABCONF0: = QS600
R149 = 0R,_0402_3: CLABCONF0: = QS600
R190 = 0R,_0402_8: CLABCONF0: = QS600
R191 = 0R,_0402_2: CLABCONF0: = QS600
R221 = 0R,_0402_7: CLABCONF0: = QS600
R222 = 4.99K,1%,0402,1_16W: CLABCONF0: = QS600; P/N: 161C44231S
RN23 = RN,10K,8P4R@0805: CLABCONF0: = QS600
RN25 = RN,0R,8P4R@0805: CLABCONF0: = QS600
C204 = 470pF,_50V,_X7R,_10%,_0603_1: CLABCONF0: DNP
C205 = 470pF,_50V,_X7R,_10%,_0603: CLABCONF0: DNP
D10 = BAT54C: CLABCONF0: = T43
Q13 = MOSFET_N_DUAL_0_0.4A_20V: CLABCONF0: = T43
Q14 = N-MOSFET,NDS335N,100mOhm@2.5V: CLABCONF0: = T43
R69 = 0R,_0402_4: CLABCONF0: = T43
R71 = 475R_1%,_0402_1: CLABCONF0: = T43
R72 = 475R_1%,_0402: CLABCONF0: = T43
R75 = 0R,_0402_3: CLABCONF0: = T43
R76 = 0R,_0402_2: CLABCONF0: = T43
R79 = 1K,1%,0402,1_16W: CLABCONF0: = T43
R87 = 0R,_0402_12: CLABCONF0: = T43
R95 = 0R,_0402_9: CLABCONF0: = T43
R96 = 0R,_0402_8: CLABCONF0: = T43
R97 = 0R,_0402_7: CLABCONF0: = T43
R98 = 0R,_0402_11: CLABCONF0: = T43
R107 = 10K,1%,0402,1_16W: CLABCONF0: = T43
R115 = 0R,_0402_10: CLABCONF0: = T43
R117 = 0R,_0402_5: CLABCONF0: = T43
R118 = 0R,_0402_13: CLABCONF0: = T43
R144 = 0R,_0402_1: CLABCONF0: = T43
R146 = 10K,1%,0402,1_16W_1: CLABCONF0: = T43
R148 = 10K,1%,0402,1_16W_2: CLABCONF0: = T43
R212 = 0R,_0402: CLABCONF0: = T43
R213 = 0R,_0402_6: CLABCONF0: = T43
RN27-RN29 = RN,0R,8P4R@0805: CLABCONF0: = T43

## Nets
AGND: P1.195(AUDIO_GND) ; also on sheet 6
GND: C1.2 C2.2 C3.2 C4.2 C5.2 C6.2 C7.2 C8.2 C9.2 C10.2 C11.2 C12.2 C141.2 C150.2 C151.2 C152.2 C153.2 C157.2 C189.2 C190.2 C191.2 C192.2 C194.2 C196.2 C200.1 C202.2 C203.2 C204.2 C205.2 C206.2 C207.2 C208.2 C209.2 C210.2 C211.2 C212.2 C213.2 C214.2 C215.2 C216.2 C217.2 C218.2 C219.2 C220.2 C221.2 C222.2 C223.2 C224.2 C225.2 C226.2 C227.2 C230.2 C231.2 C232.2 C233.2 C234.2 C235.2 C236.2 C237.2 C238.2 C239.2 C240.2 C241.2 C242.2 C243.2 C244.2 C245.2 C246.2 C247.2 C248.2 C249.2 C250.2 C251.2 C258.2 C259.2 C260.2 C261.2 C262.2 C263.2 C264.2 C265.2 C266.2 C267.2 C364.1 DS4.CATHODE DS5.CATHODE FB12.1 H1.1 H2.1 H3.1 H4.1 H5.1 H6.1 P1.1(GND1) P1.19(GND2) P1.37(GND3) P1.55(GND4) P1.71(GND5) P1.87(GND6) P1.105(GND7) P1.123(GND8) P1.141(GND9) P1.159(GND10) P1.177(GND11) Q13.1(S1) Q13.4(S2) Q14.2(S) Q19.2(S) R60.1 R71.2 R72.2 R91.1 R105.1 R107.2 R130.2 R150.1 R163.2 R164.2 R165.2 R166.2 R167.2 R171.2 R172.2 R199.2 R216.2 R329.2 R330.2 RN23.5(RD2) RN23.6(RC2) RN23.7(RB2) RN23.8(RA2) RN25.3(RC1) RN25.4(RD1) U18.2(GND) U27.3(GND) U28.4(VSS1) U28.27(VSS2) U29.1(GND) U37.4(GND) U40.2(GND) ; also on sheet 1 3 5 6 7 8 9
VBAT: C209.1 R109.1 ; also on sheet 9
VBUS0: P1.180(USBOTG_VBUS) R81.2 R108.1 R146.1 ; also on sheet 5 9
VBUS0_EN_3V3: R144.2 ; also on sheet 5
VBUS1: R87.2 ; also on sheet 5
VBUS1_EN_3V3: R149.2 ; also on sheet 5
VCC_CM: C1.1 C2.1 C3.1 C4.1 C5.1 C6.1 C7.1 C8.1 C9.1 C10.1 C11.1 C12.1 C206.1 C207.1 C208.1 P1.10(VSYS1) P1.28(VSYS2) P1.46(VSYS3) P1.64(VSYS4) P1.78(VSYS5) P1.96(VSYS6) P1.114(VSYS7) P1.132(VSYS8) P1.150(VSYS9) P1.168(VSYS10) P1.186(VSYS11) P1.204(VSYS12) R56.2 R121.1 R203.1 ; also on sheet 6 9
VDD3A_ETH: L1.1 P1.2(3V3A_ETH_PHY)
3P3_LED: DS4.ANODE R202.2
26D2U_nMR: C153.1 Q17.3(D) Q19.3(D) R159.2 R161.1 R199.1 U29.3(~{MR})
100MIL_MFUNC_PCAM_DAT10: R88.1 ; also on sheet 1
100MIL_MFUNC_PCAM_DAT11: R89.1 ; also on sheet 1
100MIL_MFUNC_PCAM_DAT12: RN24.8(RA2) ; also on sheet 1
100MIL_MFUNC_PCAM_DAT13: RN24.7(RB2) ; also on sheet 1
100MIL_MFUNC_PCAM_DAT14: RN24.5(RD2) ; also on sheet 1
100MIL_MFUNC_PCAM_DAT15: RN24.6(RC2) ; also on sheet 1
ADDN_PCIE_PER1N: RN47.8(RA2) ; also on sheet 8
ADDN_PCIE_PER1P: RN47.7(RB2) ; also on sheet 8
ADDN_PCIE_PET1N: RN47.6(RC2) ; also on sheet 8
ADDN_PCIE_PET1P: RN47.5(RD2) ; also on sheet 8
ADDN_PCIE_REFCLKN: U28.7(OUT0#) ; also on sheet 8
ADDN_PCIE_REFCLKP: U28.6(OUT0) ; also on sheet 8
ALT_BOOT_ACT: R91.2 U40.6(I2) ; also on sheet 1
ALTBOOT_LEDAN: DS12.ANODE R220.1
ALTBOOT_LEDCAT: DS12.CATHODE U40.4(Y)
ATP3V3_FB: R150.2 R154.1 U18.4(FB)
BQ24161_CD: R221.2 ; also on sheet 9
BQ_INSRC: R121.2 R145.2 R148.2 R221.1 R222.1 ; also on sheet 9
BQ_PSEL: R81.1 R104.2 ; also on sheet 9
BQ_VBUSRC_DISABLE: Q13.3(D2) R105.2 R108.2 R146.2 ; also on sheet 9
CAN_RX_3V3: R212.1 ; also on sheet 3
CAN_TX_3V3: R213.1 ; also on sheet 3
CARRIER_I2C_SCL_3V3: U28.13(SCLK) ; also on sheet 3 6 7 8
CARRIER_I2C_SCL_VPER: R66.1 R73.1 R117.1 ; also on sheet 1 6 9
CARRIER_I2C_SDA_3V3: U28.14(SDA) ; also on sheet 3 6 7 8
CARRIER_I2C_SDA_VPER: R67.1 R74.1 R118.1 ; also on sheet 1 6 9
CARRIER_SUPPLIES_EN: R56.1 R58.2 R60.2 ; also on sheet 9
CHASSIS: C194.1 FB12.2 H7.1 H8.1 H9.1 H10.1 ; also on sheet 1 3 5 6 7 8
CM_LED: DS5.ANODE R203.2
DC_IN_DET: Q14.1(G) R110.2 R148.1 ; also on sheet 9
DISPLAYSHIFTER_NOE: R86.2 ; also on sheet 7
DVI_DDC_SCL_VPER: R68.2 R75.1 ; also on sheet 7
DVI_DDC_SDA_VPER: R70.2 R76.1 ; also on sheet 7
ETH1_GREEN_LED_AN: C205.1 D10.3(CATHODE) ; also on sheet 1
ETH1_GREEN_LED_CAT: R72.1 ; also on sheet 1
ETH1_YELLOW_LED_AN: C204.1 R69.1 ; also on sheet 1
ETH1_YELLOW_LED_CAT: R71.1 ; also on sheet 1
ETH2_LED_LINK10_100: R95.1 ; also on sheet 1
ETH2_LINK-LED_1000: R96.1 ; also on sheet 1
ETH2_LINK-LED_ACT: R115.1 ; also on sheet 1
ETH2_MDI0N: RN27.2(RB1) ; also on sheet 1
ETH2_MDI0P: RN27.1(RA1) ; also on sheet 1
ETH2_MDI1N: RN27.4(RD1) ; also on sheet 1
ETH2_MDI1P: RN27.3(RC1) ; also on sheet 1
ETH2_MDI2N: RN28.2(RB1) ; also on sheet 1
ETH2_MDI2P: RN28.1(RA1) ; also on sheet 1
ETH2_MDI3N: RN28.4(RD1) ; also on sheet 1
ETH2_MDI3P: RN28.3(RC1) ; also on sheet 1
EXPANDER_nINT: R131.2 ; also on sheet 6
GP_LED: DS10.ANODE R218.2
GPLED_CAT: DS10.CATHODE ; also on sheet 6
INSRC_SBYFB: R222.2 ; also on sheet 9
MAIN_PWR_CYCLE: Q17.2(S) R160.2 U37.1(A) ; also on sheet 6
MAIN_PWR_EN: R161.2 U29.2(~{RESET}) ; also on sheet 9
MFUNC_P1-21: RN29.1(RA1) ; also on sheet 5
MFUNC_P1-23: RN29.2(RB1) ; also on sheet 5
MFUNC_P1-27: RN29.3(RC1) ; also on sheet 5
MFUNC_P1-29: RN29.4(RD1) ; also on sheet 5
MUX_DN: R190.2 ; also on sheet 5
MUX_DP: R191.2 ; also on sheet 5
nCHARGER: Q13.6(D1) R79.1 R144.1
ONESHOT_CEXT: C201.1 R216.1 U37.6(Cext)
ONESHOT_OUT: Q19.1(G) U37.5(Q)
ONESHOT_REXT: C201.2 R102.2 U37.7(Rext)
P1-3_UART2_TX: P1.3(UART2_TX) R97.1 ; also on sheet 5
P1-4_ETH_LED2_ACT: P1.4(ETH_LED2_ACT) R69.2 ; also on sheet 1
P1-5_UART2_RX: P1.5(UART2_RX) R98.1 ; also on sheet 5
P1-6_ETH_MDI0N: P1.6(MDI0-/TX-) ; also on sheet 1
P1-7_UART2_CTS: P1.7(UART2_CTS) R213.2 ; also on sheet 5
P1-8_ETH_MDI0P: P1.8(MDI0+/TX+) ; also on sheet 1
P1-9_UART2_RTS: P1.9(UART2_RTS) R212.2 ; also on sheet 5
P1-11_UART1_TX: P1.11(UART1_TX) ; also on sheet 5
P1-12_ETH_MDI1N: P1.12(MDI1-/RX-) ; also on sheet 1
P1-13_UART1_RX: P1.13(UART1_RX) ; also on sheet 5
P1-14_ETH_MDI1P: P1.14(MDI1+/RX+) ; also on sheet 1
P1-15_UART1_CTS: P1.15(UART1_CTS) R76.2 ; also on sheet 5
P1-16_ETH_LED1_SPD: D10.2(ANODE2) P1.16(ETH_LED1_SPD) ; also on sheet 1
P1-17_UART1_RTS: P1.17(UART1_RTS) R75.2 ; also on sheet 5
P1-18_ETH_MDI2N: P1.18(MDI2-) ; also on sheet 1
P1-20_ETH_MDI2P: P1.20(MDI2+) ; also on sheet 1
P1-21_SATA_TXP: P1.21(SATA_TX+) RN29.8(RA2) ; also on sheet 8
P1-22_ETH_LED3: D10.1(ANODE1) P1.22(ETH_LED3) ; also on sheet 1
P1-23_SATA_TXN: P1.23(SATA_TX-) RN29.7(RB2) ; also on sheet 8
P1-24_ETH_MDI3N: P1.24(MDI3-) ; also on sheet 1
P1-25_TMDS_DDC_SCL: P1.25(TMDS_DDC_SCL) ; also on sheet 3
P1-26_ETH_MDI3P: P1.26(MDI3+) ; also on sheet 1
P1-27_SATA_RXP: P1.27(SATA_RX+) RN29.6(RC2) ; also on sheet 8
P1-29_SATA_RXN: P1.29(SATA_RX-) RN29.5(RD2) ; also on sheet 8
P1-30_TMDS_CLKP: P1.30(TMDS_CLK+) RN27.7(RB2) ; also on sheet 3
P1-31_TMDS_DDC_SDA: P1.31(TMDS_DDC_SDA) ; also on sheet 3
P1-32_TMDS_CLKN: P1.32(TMDS_CLK-) RN27.8(RA2) ; also on sheet 3
P1-33_LVDS_CLKP: P1.33(LVDS_CLK0+) ; also on sheet 3
P1-34_HDMI_CEC: P1.34(HDMI_CEC) R95.2 ; also on sheet 3
P1-35_LVDS_CLKN: P1.35(LVDS_CLK0-) ; also on sheet 3
P1-36_TMDS_D0P: P1.36(TMDS_DAT0+) RN27.5(RD2) ; also on sheet 3
P1-38_TMDS_D0N: P1.38(TMDS_DAT0-) RN27.6(RC2) ; also on sheet 3
P1-39_LVDS_P0: P1.39(LVDS_TX0+) ; also on sheet 3
P1-40_HDMI_HPD: P1.40(TMDS_HPD) R96.2 ; also on sheet 3
P1-41_LVDS_N0: P1.41(LVDS_TX0-) ; also on sheet 3
P1-42_TMDS_D1P: P1.42(TMDS_DAT1+) RN28.7(RB2) ; also on sheet 3
P1-43_I2C2_SCL: P1.43(I2C2_SCL) R68.1 ; also on sheet 5
P1-44_TMDS_D1N: P1.44(TMDS_DAT1-) RN28.8(RA2) ; also on sheet 3
P1-45_LVDS_P1: P1.45(LVDS_TX1+) ; also on sheet 3
P1-47_LVDS_N1: P1.47(LVDS_TX1-) ; also on sheet 3
P1-48_TMDS_D2P: P1.48(TMDS_DAT2+) RN28.5(RD2) ; also on sheet 3
P1-49_I2C2_SDA: P1.49(I2C2_SDA) R70.1 ; also on sheet 5
P1-50_TMDS_D2N: P1.50(TMDS_DAT2-) RN28.6(RC2) ; also on sheet 3
P1-51_LVDS_P2: P1.51(LVDS_TX2+) ; also on sheet 3
P1-52_SPI_CS1: P1.52(SPI_CS1) ; also on sheet 5
P1-53_LVDS_N2: P1.53(LVDS_TX2-) ; also on sheet 3
P1-54_GPIO8: P1.54(GPIO8) ; also on sheet 5
P1-56_GPIO9: P1.56(GPIO9) ; also on sheet 5
P1-57_LVDS_P3: P1.57(LVDS_TX3+) R115.2 ; also on sheet 3
P1-58_SPI_CS0: P1.58(SPI_CS0) R67.2 ; also on sheet 5
P1-59_LVDS_N3: P1.59(LVDS_TX3-) ; also on sheet 3
P1-60_GPIO10: P1.60(GPIO10) ; also on sheet 5 6
P1-61_MMC0_CD: P1.61(SDCARD_CD) ; also on sheet 6
P1-62_GPIO11: P1.62(GPIO11) ; also on sheet 5
P1-63_SPI_SOMI: P1.63(SPI_SOMI) ; also on sheet 5
P1-65_SPI_SIMO: P1.65(SPI_SIMO) ; also on sheet 5
P1-66_RTOUCH_XP: P1.66(RTOUCH_X+) ; also on sheet 5 7
P1-67_MMC0_WP: P1.67(SDCARD_WP) ; also on sheet 6
P1-68_RTOUCH_XN: P1.68(RTOUCH_X-) ; also on sheet 5 7
P1-69_SPI_CLK: P1.69(SPI_CLK) R66.2 ; also on sheet 5
P1-70_RTOUCH_YP: P1.70(RTOUCH_Y+) ; also on sheet 5 7
P1-72_RTOUCH_YN: P1.72(RTOUCH_Y-) ; also on sheet 5 7
P1-73_PWM: P1.73(PWM) ; also on sheet 7
P1-74_PDISP_DATA22: P1.74(PDISP_DAT22) ; also on sheet 7
P1-75_GPIO3: P1.75(GPIO3) ; also on sheet 5
P1-76_PDISP_DATA23: P1.76(PDISP_DAT23) ; also on sheet 7
P1-77_PCAM_DAT4/100DIFF_1P: P1.77(PCAM_DAT4) ; also on sheet 1
P1-79_PCAM_DAT5/100DIFF_1N: P1.79(PCAM_DAT5) ; also on sheet 1
P1-80_MMC0_CLK: P1.80(SDCARD_CLK) ; also on sheet 6
P1-81_PCAM_SHUTTER: P1.81(PCAM_SHUTTER) ; also on sheet 1
P1-82_MMC0_CMD: P1.82(SDCARD_CMD) ; also on sheet 6
P1-83_PCAM_DAT6/100DIFF_2P: P1.83(PCAM_DAT6) ; also on sheet 1
P1-84_MMC0_DAT0: P1.84(SDCARD_DAT0) ; also on sheet 6
P1-85_PCAM_DAT7/100DIFF_2N: P1.85(PCAM_DAT7) ; also on sheet 1
P1-86_MMC0_DAT1: P1.86(SDCARD_DAT1) ; also on sheet 6
P1-88_MMC0_DAT2: P1.88(SDCARD_DAT2) ; also on sheet 6
P1-89_PCAM_DAT2/100DIFF_3N: P1.89(PCAM_DAT2) ; also on sheet 1
P1-90_MMC0_DAT3: P1.90(SDCARD_DAT3) ; also on sheet 6
P1-91_PCAM_DAT3/100DIFF_3P: P1.91(PCAM_DAT3) ; also on sheet 1
P1-92_PDISP_DATA17: P1.92(PDISP_DAT17) ; also on sheet 7
P1-93_PCAM_STROBE: P1.93(PCAM_STROBE) ; also on sheet 1
P1-94_PDISP_DATA16: P1.94(PDISP_DAT16) ; also on sheet 7
P1-95_PCAM_PCLK/100DIFF_4N: P1.95(PCAM_PCLK) ; also on sheet 1
P1-97_PCAM_WEN/100DIFF_4P: P1.97(PCAM_WEN) ; also on sheet 1
P1-98_PDISP_PCLK: P1.98(PDISP_PCLK) ; also on sheet 7
P1-99_PCAM_RESET: P1.99(PCAM_RESET) ; also on sheet 1
P1-100_PDISP_HSYNC: P1.100(PDISP_HSYNC) ; also on sheet 7
P1-101_PCAM_DAT0/100DIFF_5N: P1.101(PCAM_DAT0) ; also on sheet 1
P1-102_PDISP_VSYNC: P1.102(PDISP_VSYNC) ; also on sheet 7
P1-103_PCAM_DAT1/100DIFF_5P: P1.103(PCAM_DAT1) ; also on sheet 1
P1-104_PDISP_DE: P1.104(PDISP_DE) ; also on sheet 7
P1-106_PDISP_DATA00: P1.106(PDISP_DAT0) ; also on sheet 7
P1-107_PCAM_DAT8/100DIFF_6N: P1.107(PCAM_DAT8) ; also on sheet 1
P1-108_PDISP_DATA01: P1.108(PDISP_DAT1) ; also on sheet 7
P1-109_PCAM_DAT9/100DIFF_6P: P1.109(PCAM_DAT9) ; also on sheet 1
P1-110_PDISP_DATA02: P1.110(PDISP_DAT2) ; also on sheet 7
P1-111_UARTDBG_TX: P1.111(UARTDBG_TX) R120.1 ; also on sheet 6
P1-112_PDISP_DATA03: P1.112(PDISP_DAT3) ; also on sheet 7
P1-113_PCAM_VSYNC/100DIFF_7P: P1.113(PCAM_VSYNC) ; also on sheet 1
P1-115_PCAM_HSYNC/100DIFF_7N: P1.115(PCAM_HSYNC) ; also on sheet 1
P1-116_PDISP_DATA04: P1.116(PDISP_DAT4) ; also on sheet 7
P1-117_UARTDBG_RX: P1.117(UARTDBG_RX) R119.1 ; also on sheet 6
P1-118_PDISP_DATA05: P1.118(PDISP_DAT5) ; also on sheet 7
P1-119_PCIE_REFCLKP: P1.119(PCIE_REFCLK+) R89.2 R124.2 R186.1 ; also on sheet 8
P1-120_PDISP_DATA06: P1.120(PDISP_DAT6) ; also on sheet 7
P1-121_PCIE_REFCLKN: P1.121(PCIE_REFCLK-) R88.2 R125.2 R185.1 ; also on sheet 8
P1-122_PDISP_DATA07: P1.122(PDISP_DAT7) ; also on sheet 7
P1-124_PDISP_DATA08: P1.124(PDISP_DAT8) RN23.4(RD1) ; also on sheet 7
P1-125_PCIE_TXP: P1.125(PCIE_TX+) RN24.3(RC1) ; also on sheet 8
P1-126_PDISP_DATA09: P1.126(PDISP_DAT9) RN23.3(RC1) ; also on sheet 7
P1-127_PCIE_TXN: P1.127(PCIE_TX-) RN24.4(RD1) ; also on sheet 8
P1-128_PDISP_DATA10: P1.128(PDISP_DAT10) RN23.2(RB1) ; also on sheet 7
P1-129_I2C3_SCL: P1.129(I2C3_SCL) R117.2
P1-130_PDISP_DATA11: P1.130(PDISP_DAT11) RN23.1(RA1) ; also on sheet 7
P1-131_PCIE_RXP: P1.131(PCIE_RX+) RN24.1(RA1) ; also on sheet 8
P1-133_PCIE_RXN: P1.133(PCIE_RX-) RN24.2(RB1) ; also on sheet 8
P1-134_PDISP_DATA12: P1.134(PDISP_DAT12) ; also on sheet 7
P1-135_I2C3_SDA: P1.135(I2C3_SDA) R118.2
P1-136_PDISP_DATA13: P1.136(PDISP_DAT13) ; also on sheet 7
P1-137_I2S1_CLKX: P1.137(I2S1_CLKX) ; also on sheet 5
P1-138_PDISP_DATA14: P1.138(PDISP_DAT14) ; also on sheet 7
P1-139_I2S1_DOUT: P1.139(I2S1_DOUT) ; also on sheet 5
P1-140_PDISP_DATA15: P1.140(PDISP_DAT15) ; also on sheet 7
P1-142_PDISP_DATA18: P1.142(PDISP_DAT18) ; also on sheet 7
P1-143_I2S1_DIN: P1.143(I2S1_DIN) ; also on sheet 5
P1-144_PDISP_DATA19: P1.144(PDISP_DAT19) ; also on sheet 7
P1-145_I2S1_FSX: P1.145(I2S1_FSX) ; also on sheet 5
P1-146_PDISP_DATA20: P1.146(PDISP_DAT20) ; also on sheet 7
P1-147_SDIO_CMD: P1.147(SDIO_CMD) ; also on sheet 5
P1-148_PDISP_DATA21: P1.148(PDISP_DAT21) ; also on sheet 7
P1-149_SDIO_DAT3: P1.149(SDIO_DAT3) ; also on sheet 5
P1-151_SDIO_DAT2: P1.151(SDIO_DAT2) ; also on sheet 5
P1-152_GPIO1: P1.152(GPIO1) ; also on sheet 5 9
P1-153_SDIO_DAT1: P1.153(SDIO_DAT1) ; also on sheet 5
P1-154_GPIO2: P1.154(GPIO2) ; also on sheet 5
P1-155_SDIO_DAT0: P1.155(SDIO_DAT0) ; also on sheet 5
P1-156_USBPWREN: P1.156(USB_PWREN) ; also on sheet 5
P1-157_SDIO_CLK: P1.157(SDIO_CLK) ; also on sheet 5
P1-158_HSUSB3_DN: P1.158(HSUSB3_D-) ; also on sheet 5
P1-160_HSUSB3_DP: P1.160(HSUSB3_D+) ; also on sheet 5
P1-161_GPIO4: P1.161(GPIO4) R73.2 R131.1 ; also on sheet 5
P1-162_nOVC: P1.162(USB_nOVC) ; also on sheet 5
P1-163_GPIO5: P1.163(GPIO5) R74.2 ; also on sheet 5
P1-164_HSUSB2_DN: P1.164(HSUSB2_D-) R190.1 ; also on sheet 5
P1-165_PWRON: P1.165(PWRON) ; also on sheet 1
P1-166_HSUSB2_DP: P1.166(HSUSB2_D+) R191.1 ; also on sheet 5
P1-167: P1.167 RN47.1(RA1) ; also on sheet 5
P1-169: P1.169 RN47.2(RB1) ; also on sheet 5
P1-170_HSUSB1_DN: P1.170(HSUSB1_D-) ; also on sheet 5
P1-171_COLD_RESET_IN: P1.171(COLD_RESET_IN) ; also on sheet 1
P1-172_HSUSB1_DP: P1.172(HSUSB1_D+) ; also on sheet 5
P1-173: P1.173 RN47.3(RC1) ; also on sheet 5
P1-174_USBOTG_ID: P1.174(USBOTG_ID) ; also on sheet 5
P1-175: P1.175 RN47.4(RD1) ; also on sheet 5
P1-176_USBOTG_DP: P1.176(HSUSB0_D+) ; also on sheet 5
P1-178_USBOTG_DN: P1.178(HSUSB0_D-) ; also on sheet 5
P1-179_RESERVED2: P1.179(RESERVED2) RN25.6(RC2) ; also on sheet 5
P1-181_RESERVED3: P1.181(RESERVED3) Q14.3(D) R110.1 R145.1 RN25.5(RD2)
P1-182_MFUNC: RN32.5(RD2) ; also on sheet 5
P1-182_USBSS_RXP: P1.182(SSUSB_RX+) RN32.4(RD1) ; also on sheet 5
P1-183_BKBAT: P1.183(BACKUP_BAT) R136.1 ; also on sheet 9
P1-184_MFUNC: RN32.6(RC2) ; also on sheet 5
P1-184_USBSS_RXN: P1.184(SSUSB_RX-) RN32.3(RC1) ; also on sheet 5
P1-185_ALT_BOOT: P1.185(ALT_BOOT) R90.1 U40.1(I1) U40.3(I0) ; also on sheet 1
P1-187_nRESET_WARM: P1.187(nRESET_WARM) ; also on sheet 5
P1-188_MFUNC: RN32.7(RB2) ; also on sheet 5
P1-188_USBSS_TXP: P1.188(SSUSB_TX+) RN32.2(RB1) ; also on sheet 5
P1-189_EEPROM_WP: P1.189(EEPROM_WP) ; also on sheet 1
P1-190_MFUNC: RN32.8(RA2) ; also on sheet 5
P1-190_USBSS_TXN: P1.190(SSUSB_TX-) RN32.1(RA1) ; also on sheet 5
P1-191_MICBIAS: P1.191(ANALOG_MICBIAS/MICIN+) ; also on sheet 6
P1-192_RESERVED: P1.192(RESERVED4) Q13.2(G1) Q13.5(G2) R104.1 R107.1 R109.2
P1-193_MICIN: P1.193(ANALOG_MICIN/MICIN-) ; also on sheet 6
P1-194_GPIO6: P1.194(GPIO6) ; also on sheet 5 7
P1-196_BOOT_PWR_IN: C196.1 P1.196(BOOT_PWR_IN) R87.1 R103.1
P1-197_RLINEIN: P1.197(ANALOG_RIN) ; also on sheet 6
P1-198_PER_PWREN_OUT: P1.198(PER_PWREN_OUT) ; also on sheet 5
P1-199_LLINEIN: P1.199(ANALOG_LIN) ; also on sheet 6
P1-200_GPIO7: P1.200(GPIO7) R79.2 R149.1
P1-201_RHPOUT: P1.201(ANALOG_ROUT) ; also on sheet 6
P1-202_PER_PWREN_REQ: P1.202(PER_PWREN_REQ) R58.1
P1-203_LHPOUT: P1.203(ANALOG_LOUT) ; also on sheet 6
PCIE0_nPERST_3V3: R128.2 ; also on sheet 6 8
PCIE0_REFCLKN: R183.2 ; also on sheet 8
PCIE0_REFCLKP: R184.2 ; also on sheet 8
PCIE1_nPERST_3V3: R128.1 ; also on sheet 6 8
PCIE_CLKSRC_VDDA: C141.1 L27.2 U28.28(VDD_A)
PCIE_REFCLK_CLKN_OSC: R123.1 U27.5(\\~{OU}T)
PCIE_REFCLK_CLKP_OSC: R181.1 U27.4(OUT)
PCIE_REFCLKN: R123.2 R125.1 R330.1 U28.3(SRC#)
PCIE_REFCLKP: R124.1 R181.2 R329.1 U28.2(SRC)
PCIE_REFCLKSRC_IREF: R130.1 U28.26(Iref)
PCIE_REFCLKSRC_nPWRDWN: R167.1 RN15.4(R4) U28.15(PWRDWN#) ; also on sheet 6
PCIE_REFCLKSRC_nSTOP: R164.1 RN15.3(R3) U28.16(SRC_STOP#) ; also on sheet 6
PCIE_REFCLKSRC_OE0: R166.1 RN15.1(R1) U28.8(OE_0) ; also on sheet 6
PCIE_REFCLKSRC_OE3: R163.1 RN15.2(R2) U28.21(OE_3) ; also on sheet 6
PCIE_REFCLKSRC_OEINV: R165.1 R173.1 U28.25(OE_INV) ; also on sheet 6
PCIE_REFCLKSRC_OUT2N: R185.2 U28.19(OUT2#)
PCIE_REFCLKSRC_OUT2P: R186.2 U28.20(OUT2)
PCIE_REFCLKSRC_OUT3N: R183.1 U28.22(OUT3#)
PCIE_REFCLKSRC_OUT3P: R184.1 U28.23(OUT3)
PCIE_REFCLKSRC_PLL: R171.1 RN15.6(R5) U28.12(PLL/BYPASS#) ; also on sheet 6
PCIE_REFCLKSRC_PLLBW: R172.1 RN15.7(R6) U28.17(PLL_BW#) ; also on sheet 6
PMIDU: R103.2 ; also on sheet 9
RS232_RXD: R119.2 ; also on sheet 6
RS232_TXD: R120.2 ; also on sheet 6
UARTDBG_RX: R98.2 ; also on sheet 6
UARTDBG_TX: R97.2 ; also on sheet 6
VCTAP: L1.2 ; also on sheet 1
VDC_ATP3V3: C157.1 C238.1 C239.1 R102.1 R136.2 R154.2 R159.1 U18.5(OUT) U29.4(VCC) U37.2(B) U37.3(CLR) U37.8(VCC)
VDC_IN: C152.1 U18.1(IN) U18.3(~{SHDN}) ; also on sheet 8 9
VSB_3V3: C150.1 C151.1 C189.1 C190.1 C191.1 C192.1 C202.1 C203.1 C210.1 C211.1 C212.1 C213.1 C214.1 C215.1 C216.1 C217.1 C218.1 C219.1 C220.1 C221.1 C222.1 C223.1 C224.1 C225.1 C226.1 C227.1 C230.1 C231.1 C232.1 C233.1 C234.1 C235.1 C236.1 C237.1 C240.1 C241.1 C242.1 C243.1 C244.1 C245.1 C246.1 C247.1 C248.1 C249.1 C250.1 C251.1 C258.1 C259.1 C260.1 C261.1 C262.1 C263.1 C264.1 C265.1 C266.1 C267.1 C364.2 L27.1 Q17.1(G) R160.1 R173.2 R202.1 R218.1 RN15.5(COM1) RN15.10(COM2) U27.1(OE) U27.6(VCC) U28.1(VDD1) U28.5(VDD2) U28.11(VDD3) U28.18(VDD4) U28.24(VDD5) ; also on sheet 1 3 5 6 7 8 9
VSB_PER: C200.2 R86.1 R90.2 R220.2 U40.5(VCC) ; also on sheet 1 3 5 6 7 9

Not connected (* = marked no-connect by the designer): RN15 8(R7)* 9(R8)*; RN25 1(RA1)* 2(RB1)* 7(RB2)* 8(RA2)*; U27 2(NC)*; U28 9(OUT1)* 10(OUT1#)*

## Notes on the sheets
sheet 10
- ALTERNATE BOOT SEQUENCE ENABLED
   LED
- Carrier Board
  Peripherals
  Power
  LED
- SoM/CoM
  Primary
  Power
  LED
- REF PLANE STITCHING CAPACITORS
- LED is on when alternate boot sequence is enabled
- U40 output = INPUT0 * (NOT INPUT2) + INPUT2 * (NOT INPUT 1)
- LED ON when ALT_BOOT is same level as ALT_BOOT_ACT, LED OFF otherwise
- DNP
- Carrier Board
  GPIO Controlled
  LED
- DNP
- CoM/SoM Mechanic
  Holes
- BYPASS ONBOARD RTC BATTERY
- DNP
- Carrier Board Mechanic
  Holes
- DNP
- DNP
- DNP
sheet 11
- SB-SOM-T54 Specific Provisions
  Populated only for SB-SOM-T54
- SB-SOM-T54 PRIMARY POWER from USB-OTG
- Allows CM-T54 to operate
  from VBUS0 (overcoming
  the initial 100mA current
  limit of USB), as described
  in CM-T54 reference manual
  chapter 5.5
- SB-SOM-T54 PRIMARY I2C BUS
- SB-SOM-T54 PRIMARY DEBUG UART/RS-232
- SB-SOM-T54 I2C USED FOR DVI DDC
- SB-SOM-T54 AC-Adapter detection
- P1-181 = VAC_DETECT
  VAC_DETECT Default settings:
  1. VAC_OK ON request is registered by CM-T54
  upon rising of VAC_DETECT voltage above 3.6V(max),
  or falling of VAC_DETECT voltage below 2.8V(min)
  2. In case VCC_CM & BACKUP Battery are not available
  while VAC_DETECT rises above 3.6V(max), CM-T54
  transitions from "NO SUPPLY" power state
  to "BACKUP" power state.
  3. This CM-T54 input is tolerant to voltages between 0V & 10V
sheet 12
- Additional PCI-E Provisions
  (Not Populated by default)
- CARRIER SUPPLIES
   ENABLE LOGIC
- Provision to source PCIE0
  REFCLK from GENERATOR
  to mini-PCI-E connector
- 2nd PCI-Express Provision
- POPULATE ONLY FOR
  SB-SOM-****-ATP
- Using pins 161, 163,
  165 & 167 of the SoM interface
  as PCI-Express RX & TX
- DO NOT POPULATE FOR
  SB-SOM-****-ATP
- DNP
- Provision to drive REFCLK
  GENERATOR from CoM/SoM
  sourced PCIE0 REFCLK
- Provision to source generator
  source REFCLK from onboard
  source (U27)
- T54 (default) drives this high (VCC_CM) as part of powering-up.
  T43 (default) pulls this signal up to 3.3V, SW should drive low here when T43 is in low power modes to disable carrier board supplies.
  QS600: remove R58, a voltage divider formed by R56 & R60 should result in constant voltage between 1.5V and 3.3V on
  "CARRIER_SUPPLIES_EN" pin.
- Provision to allow cloning of a CoM/SoM
  generated PCIE-Express REFCLK, into
  PCI-Express devices on the carrier
- Provision to allow driving a carrier board
  generated PCI-Express REFCLK into the CoM/SoM
  (through PCI-E0 refclk signals)
- SB-SOM PCI-Express REFCLK generator
  Provsion
- PCI-Express BYPASS
- Allows using the PCI-Express lane differential pairs
  for alternate functions through a 100MIL header.
  Useful with CoM/SoM where PCI-Express function is
  not available
- POPULATE
  ONLY
  FOR:
  SB-SOM-T54
  SB-SOM-T43
- DNP
- DNP
- DNP
- DNP
- DNP
- DNP
- DNP
- DNP
- 7-bit I2C address:
  0b110,1110
- PRODUCTION SPECIFIC PROVISIONS
   not assembled by default
- USB3.0 BYPASS
- Vout=Vfb*(1+Rt/Rb)=1.235*(1+20/11.8)=3.328V
- DNP
- NOTE:
  This circuitry allows a GPIO to generate a
  full  board power-cycle.
  The following conditions must be met for
  this circuit to work
  as designed:
  1. All board supplies must be always
  enabled
  1.1. R58 & R60 removed
  1.2. R56 assembled
  2. DC supply contorl must be controlled by
  U29
  2.1. R122 assembled
  3. Primary board power must not be
  supplied through a Li-Poly Battery or USB.
- DNP
- Allows using the USB 3.0 RX & TX differential pairs
  for alternate functions through a 100MIL header.
  Useful with CoM/SoM where USB3.0 function is
  not available
- DNP
- DNP
- U29 RESET output remains low while U29  VCC  is
  below 2.93V or when U29 MR input is low. U29 RESET
  then remains low for a minimum of 20 ms after U29
  VCC  rises above 2.93V.
  U29 MR input is an active low debounced input, which
  accepts input (low) pulses of greater than 1 µs.
- DNP
- U37 is an optional oneshot circuitry
  can only be used in case Q17 is not populated
- POPULATE
  ONLY
  FOR:
  SB-SOM-QS600
  SB-SOM-T43
- DNP
- DNP
- DNP
- DNP
- Boardwide power Cycle is triggered by a low,
  1uS (min) pulse on the MAIN_PWR_CYCLE
  signal
- Reset supervisor
  bypass:
  NOTE: the superivsor
  might be needed to ensure power
  supply outputs discharge enough
  before power is enabled again.
- Do not assemble
   for T43/QS600
sheet 13
- SB-SOM-T43 Specific Provisions
  Populated only for SB-SOM-T43
- Ethernet LED polarity
- While in most cases the ethernet LED
  control signals (SoM pins 4, 16 & 22)
  are active Low, CM-T43 ethernet leds
  are active high.
  This provision  allows correct LED
  control with SB-SOM-T43
- DNP
- DNP
- Alternate usage of SATA signals
- CM-T43 does not implement the SATA interface.
  This provision allows SB-SOM-T43 to route signals otherwise
  used for SATA, to a 100mil header
- SB-SOM-T43 PRIMARY I2C BUS
- SB-SOM-T43 CAN BUS
- SB-SOM-T43 PRIMARY DEBUG UART/RS-232
- SB-SOM-T43 I2C USED FOR DVI DDC
- USB1 Host VBUS monitoring
- CM-T43 does not implement the BOOT_PWR_IN function on carrier board
  interface pin 196.
  This provision allows CM-T43 to monitor VBUS1 with SB-SOM-T43 board.
- SB-SOM-T43 AC POWER & Detection
- CM-T43 pin 181 = AC_DET
  AC_DET Default settings:
  1. Pulled to VCC_CM onboard CM-T43
  2. Falling edge on AC_DET triggers
  transition of CM-T43 from OFF/SUSPED
  to WAIT_PWR_EN state.
  Normally, CM-T43 then transitions from
  WAIT_PWR_EN to ACTIVE state within
  20seconds.
- USB CHARGER LOGIC
- CM-T43 drives P1-192_RESERVED
  HIGH (3.3V) whenever a USB charger is
  detected on the device/host USB port
  (pins 176 & 178).
  This circuitry will make sure of the following:
  When CM-T43 detects a charger
  1. Carrier board cannot generate VBUS0
  2. VCC_CM generation from VBUS0 is allowed
  When CM-T43 does not detect a charger
  1. Carrier board can generate VBUS0
  2. VCC_CM cannot be generated from VBUS0
- CM-T43 2nd ETHERNET
  (Alternate usage
   of HDMI signals)
- LVDS SOURCE
- The LVDS display connector is driven by
  the SB-SOM-T43 onboard RGB-to-LVDS
  transceiver since CM-T43 does not implement
  the LVDS interface on the SoM itself
- CM-T43 does not  implement the HDMI interface.
  CM-T43 implements a 2nd ethernet interface, using
  the signals normally used for HDMI.
  This provision allows SB-SOM-T43 to route signals otherwise used for HDMI,
  to the secondary RJ-45 connector allowing SB-SOM-T43
  to make use of the 2nd  ethernet port available with CM-T43
sheet 14
- SB-SOM-QS600 Specific Provisions
  Populated only for SB-SOM-QS600
- SB-SOM-QS600 USB HOST POWER CONTROL
- SB-SOM-XXX uses the 3.3V USBPWR_EN function on pin 156 of SoM/CoM
   interface to enable VBUS (VBUS1 rail) for the USB Hub / P26 USB conenctor (page8).
  Using pin 156 with SB-SOM-QS600 is not possible since a 3.3V signal is
  required to enable VBUS1, while a 1.8V GPIO is routed to pin 156
  onboard CM-QS600.
  To overcome this, we are using pin 200 of CM-QS600
  interface, (which has 3.3V GPIO functionality with all CM-QS600 configurations),
  with SB-SOM-QS600, allowing VBUS1 control by means of 3.3V GPIO.
- SB-SOM-QS600 USB Hub upstream port
- Normally, SB-SOM-XXX uses the SoM USB2.0 port on pins
  170 & 172 as the upstream USB port of the carrier USB Hub
  (page8). CM-QS600 does not implement a USB2.0 interface
  on pins 170 & 172.
  To overcome this, we are using the USB port CM-QS600
  implements on pins 164 & 166 as the upstream USB port of
  SB-SOM-QS600 USB Hub
- CM-QS600 BOOT STRAPS & SEQUENCES
- Normal Boot sequence:
  1st device: CM-QS600 onboard  eMMC.
  2nd device: None
  Alternate Boot Sequence:
  1st device: SD card in SB-SOM-QS600 full size SD slot
  2nd device (if bootloader no found in first device):  CM-QS600
  onboard eMMC.
- NOTE:
  While the ALT_BOOT signal logic of most CoM/SoMs is as follows:
  0 ==> Normal Boot Sequence
  1 ==> Alternate Boot Sequence
  CM-QS600 ALT_BOOT signal logic is inverted as shown below:
  0 ==> Alternate Boot Sequence.
  1 ==> Normal boot sequence.
- Power-Down Parallel RGB Shifters
- Keep Parallel RGB interface disabled with SB-SOM-QS600
  since this interface is not available with CM-QS600 SoM/CoM
- SB-SOM-QS600 PRIMARY I2C BUS
- SB-SOM-QS600 POWER
- SB-SOM-QS600 power from USB is not supported.
  BQ24161 VBUS input is always disabled
- This enables operation of CM-QS600 from battery
  Please note that while CM-QS600 power can be supplied directly from
  battery, most carrier board components require DC power source to be
  available for normal operation
- This makes sure U25 is in HIGH-Z
  mode as soon as voltage
  BQ_INSRC is available
- This makes sure BQ_INSRC voltage is set to
  0.92*(1+(442*47/442+47)/10)=4.828V instead of 5.244.
  ensuring that VCC_CM is a valid input voltage for both
  CM-QS600 and the 5V boost (U21)
- This bypasses U25 entirely, so
  that VCC_CM is valid for
  CM-QS600 ( 4.35V < VCC_CM <
  5.5V )
- SB-SOM-QS600 GPIO Expander Interrupt
- SB-SOM-XXX uses the GPIO function on pin 60 of SoM/CoM interface
  as an interrupt for SB-SOM-XXX onboard gpio-expander.
  Using pin 60 with CM-QS600 is not possible since
  no GPIO is available on CM-QS600 pin 60 under certain
  conditions (with WB option of SoM).
  To overcome this we are using pin 161 of SoM/CoM interface, (which
  has GPIO functionality with all CM-QS600 configurations), with SB-SOM-QS600
- SB-SOM-QS600 Ethernet LEDs
- NOTE: QS600 ethernet controller must be
  properly configured for ethernet LEDs to
  operate correctly since default config
  does not comply with SODIMM204 pinout
sheet 15
- TBD
